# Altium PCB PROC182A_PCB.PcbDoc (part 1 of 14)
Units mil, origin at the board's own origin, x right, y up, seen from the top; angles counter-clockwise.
Board outline 3168.31 x 3700.79 mil, 8 copper layers (Top Layer, L2_GND1, L3_SIG1, L4_PWR1, L5_PWR2, L6_SIG2, L7_GND2, Bottom Layer), stack 58.1 mil thick; 580 components, 391 nets, 8314 pads, 4370 vias.
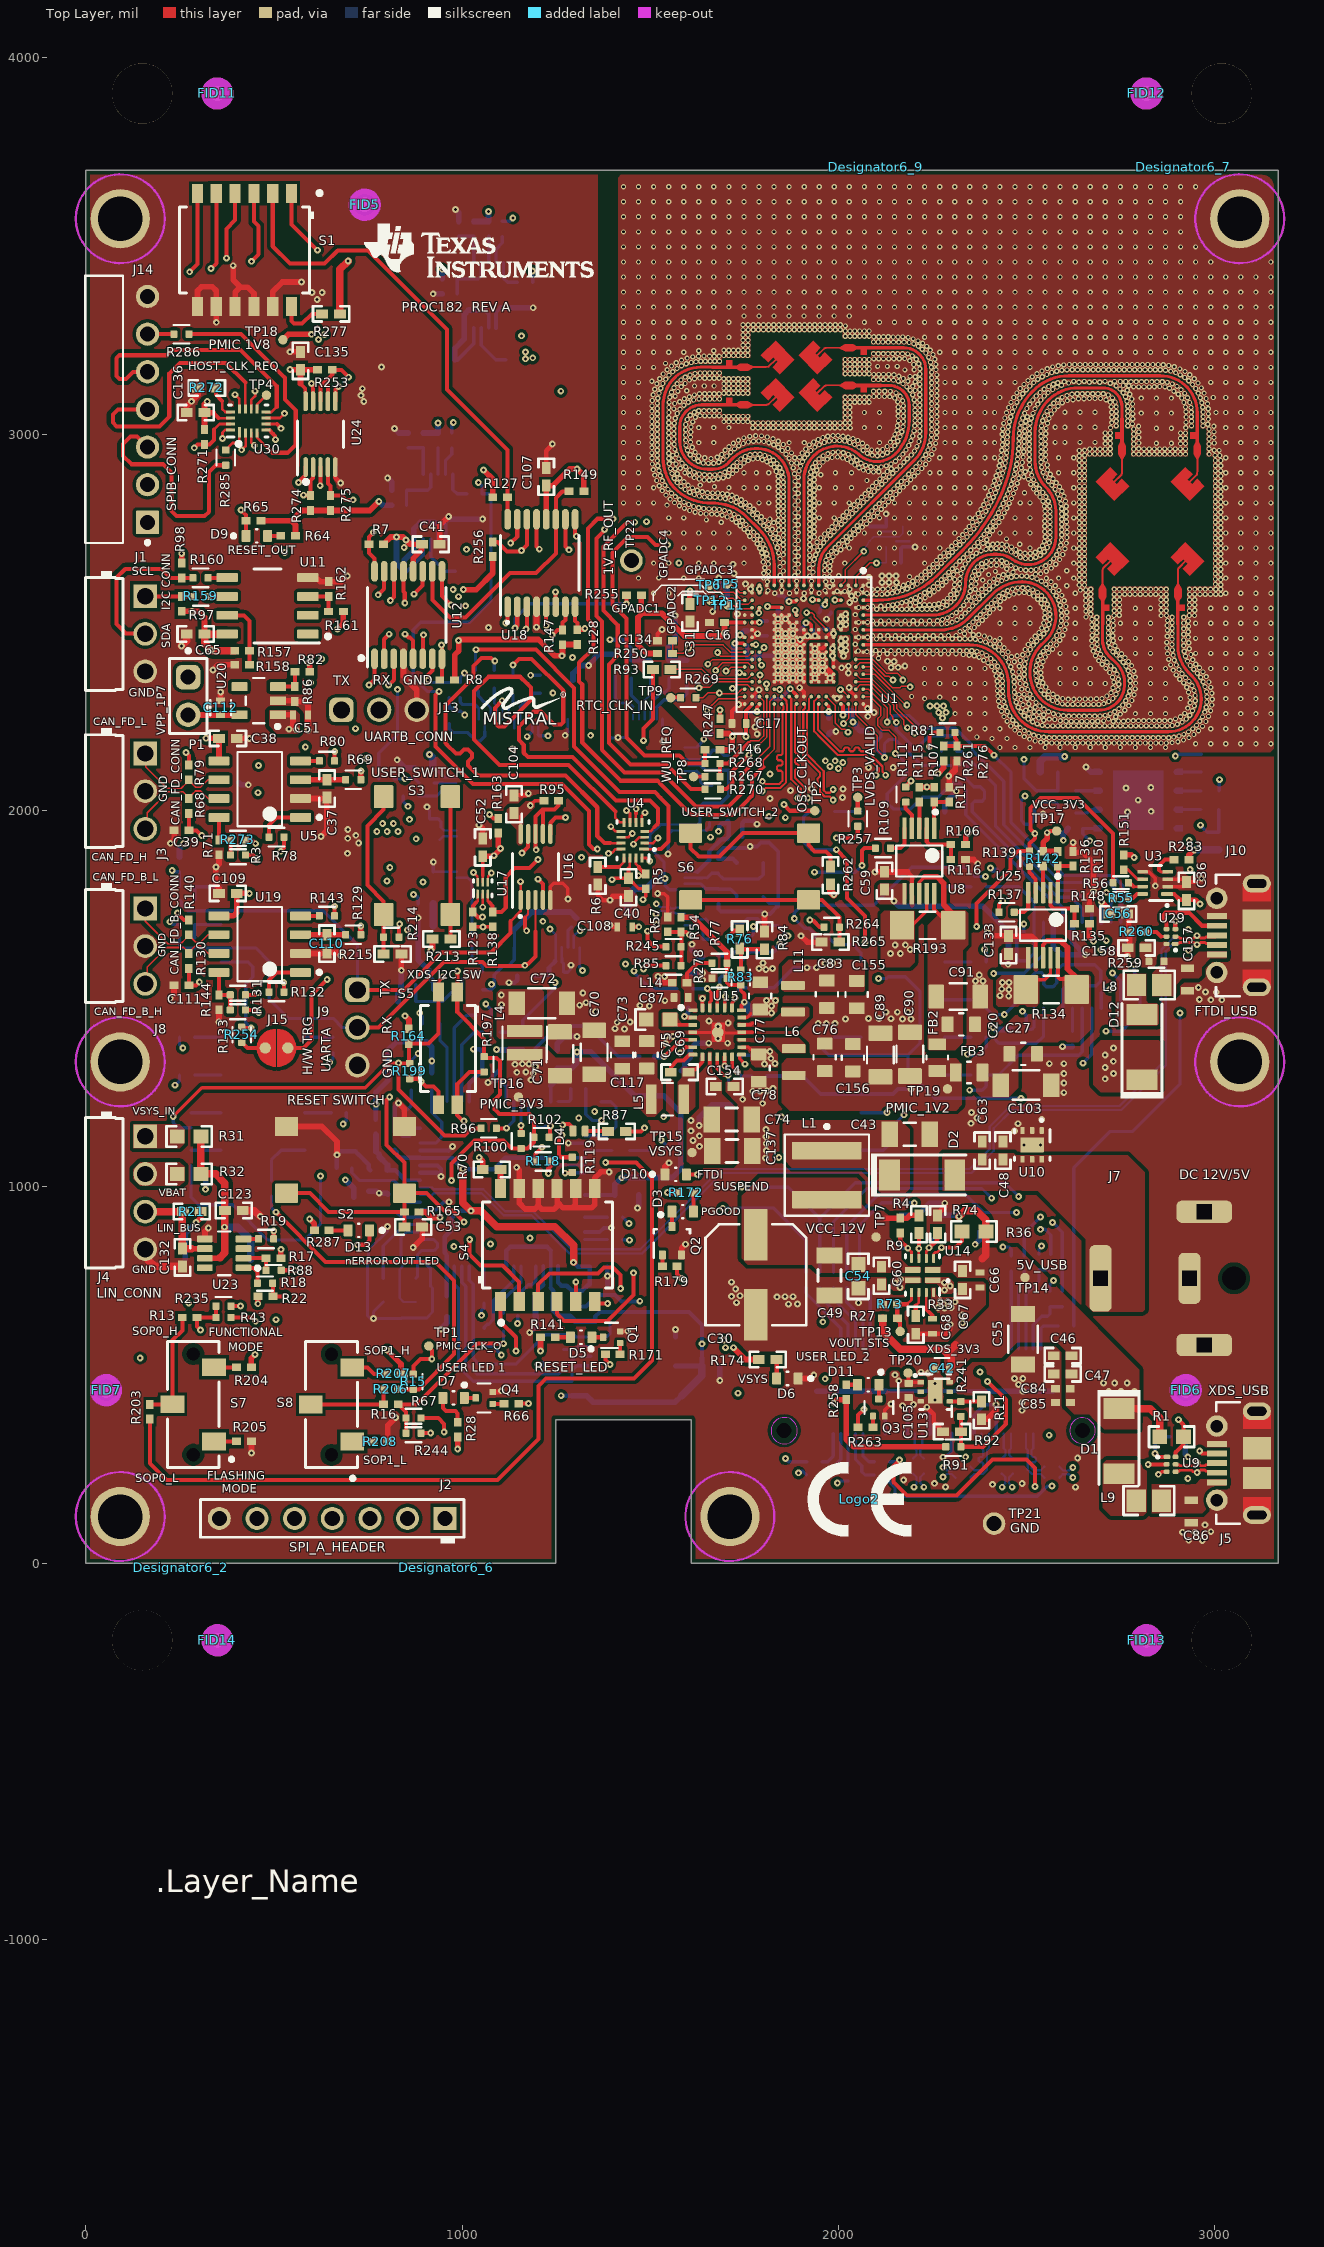
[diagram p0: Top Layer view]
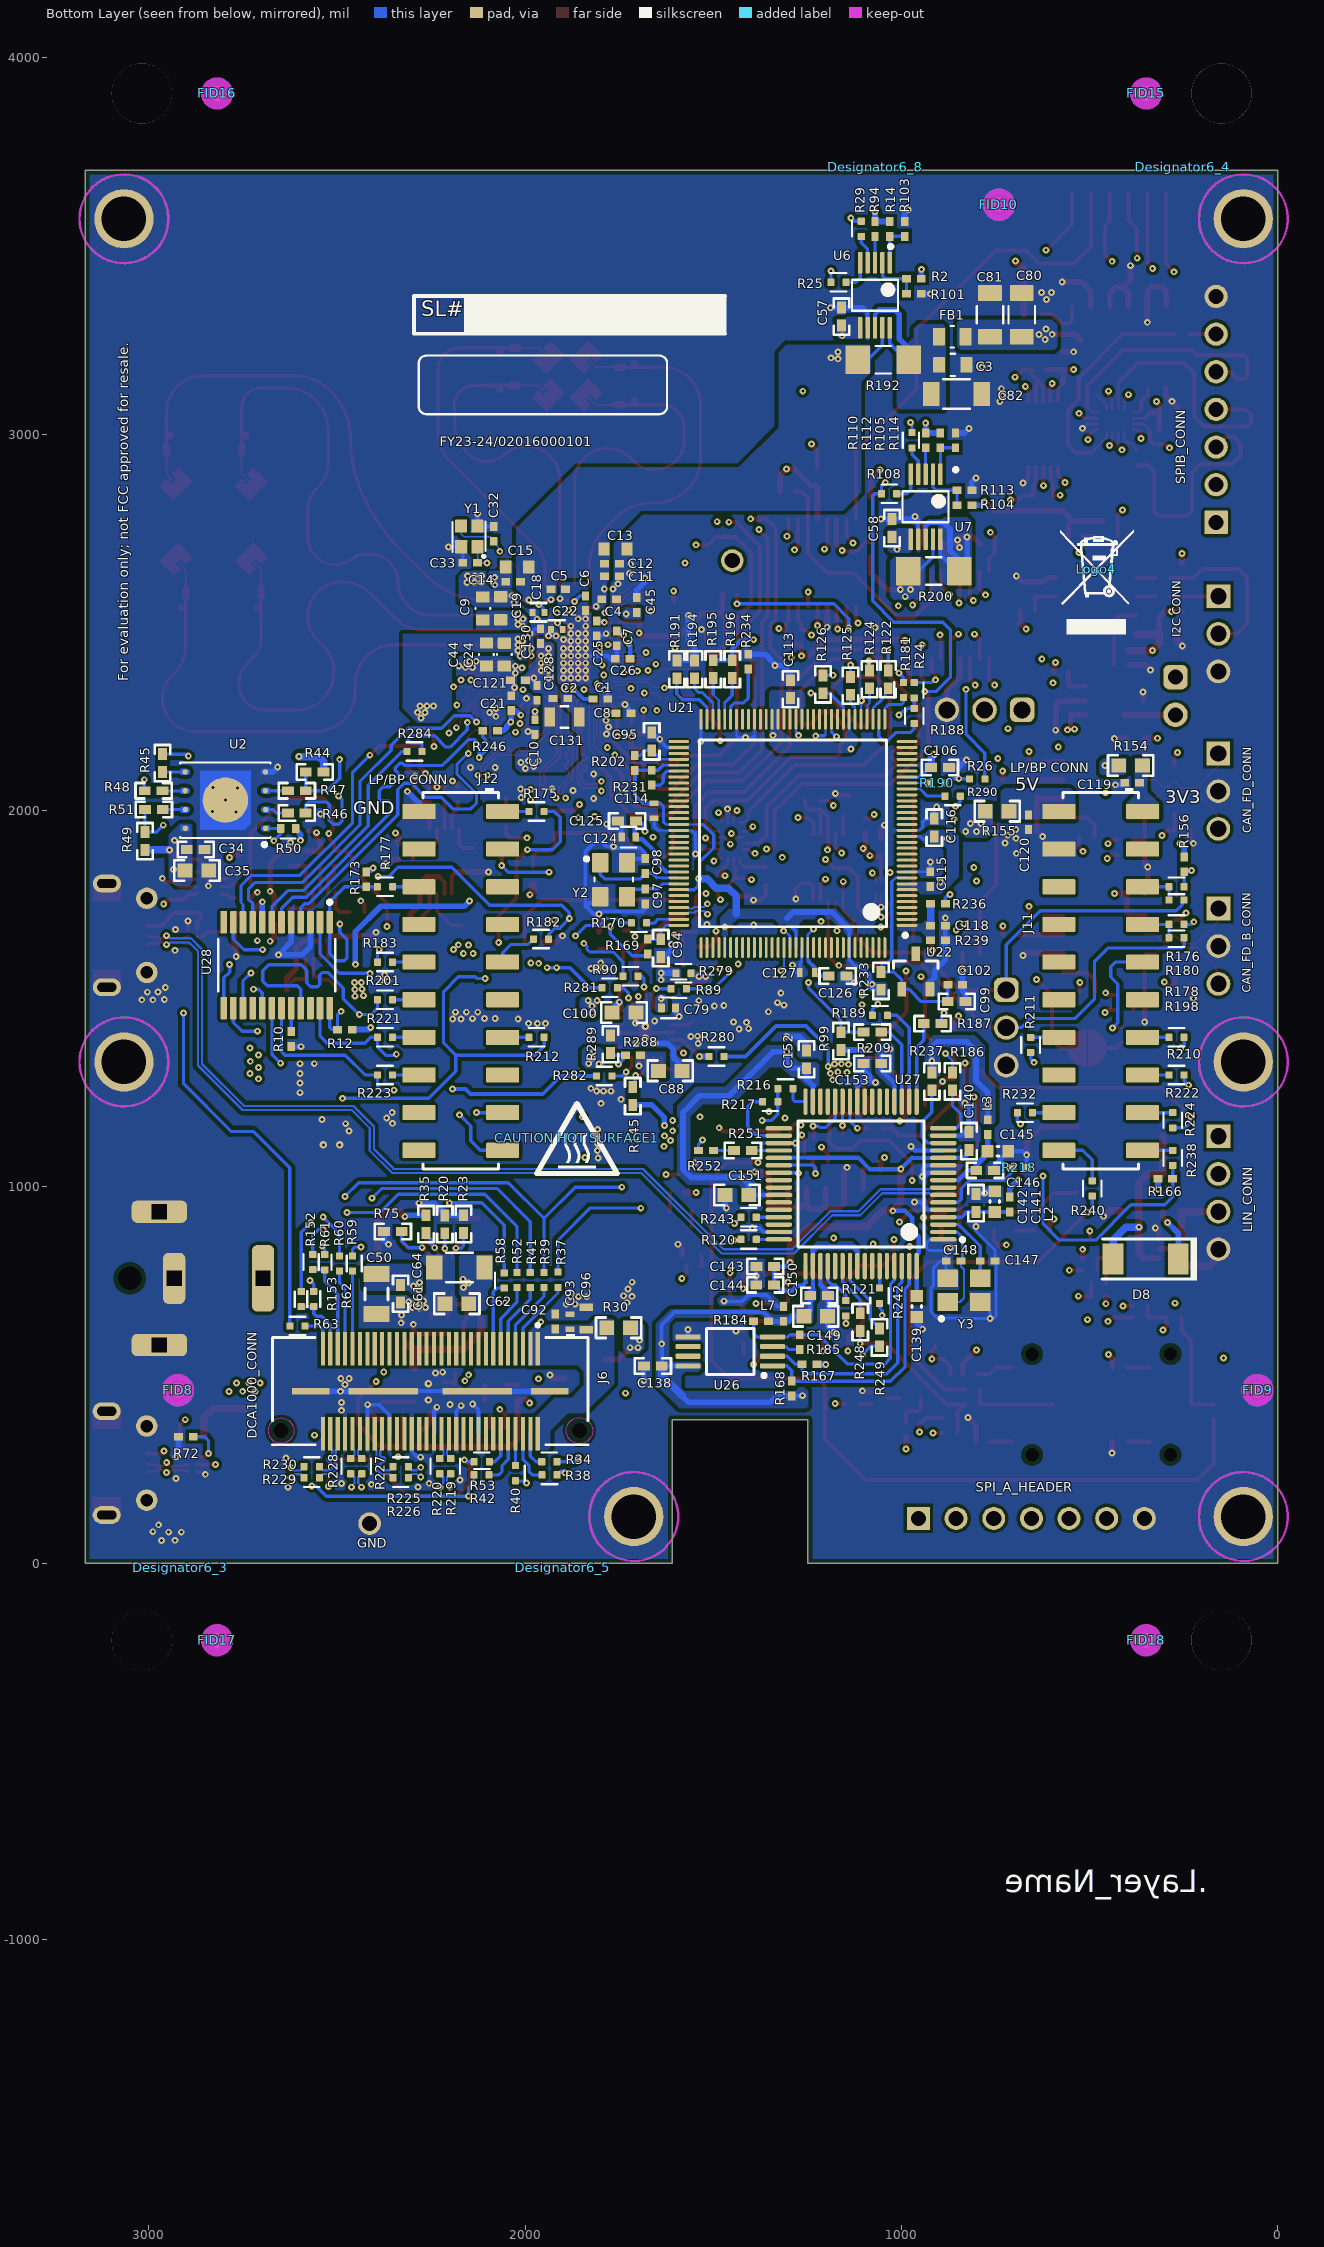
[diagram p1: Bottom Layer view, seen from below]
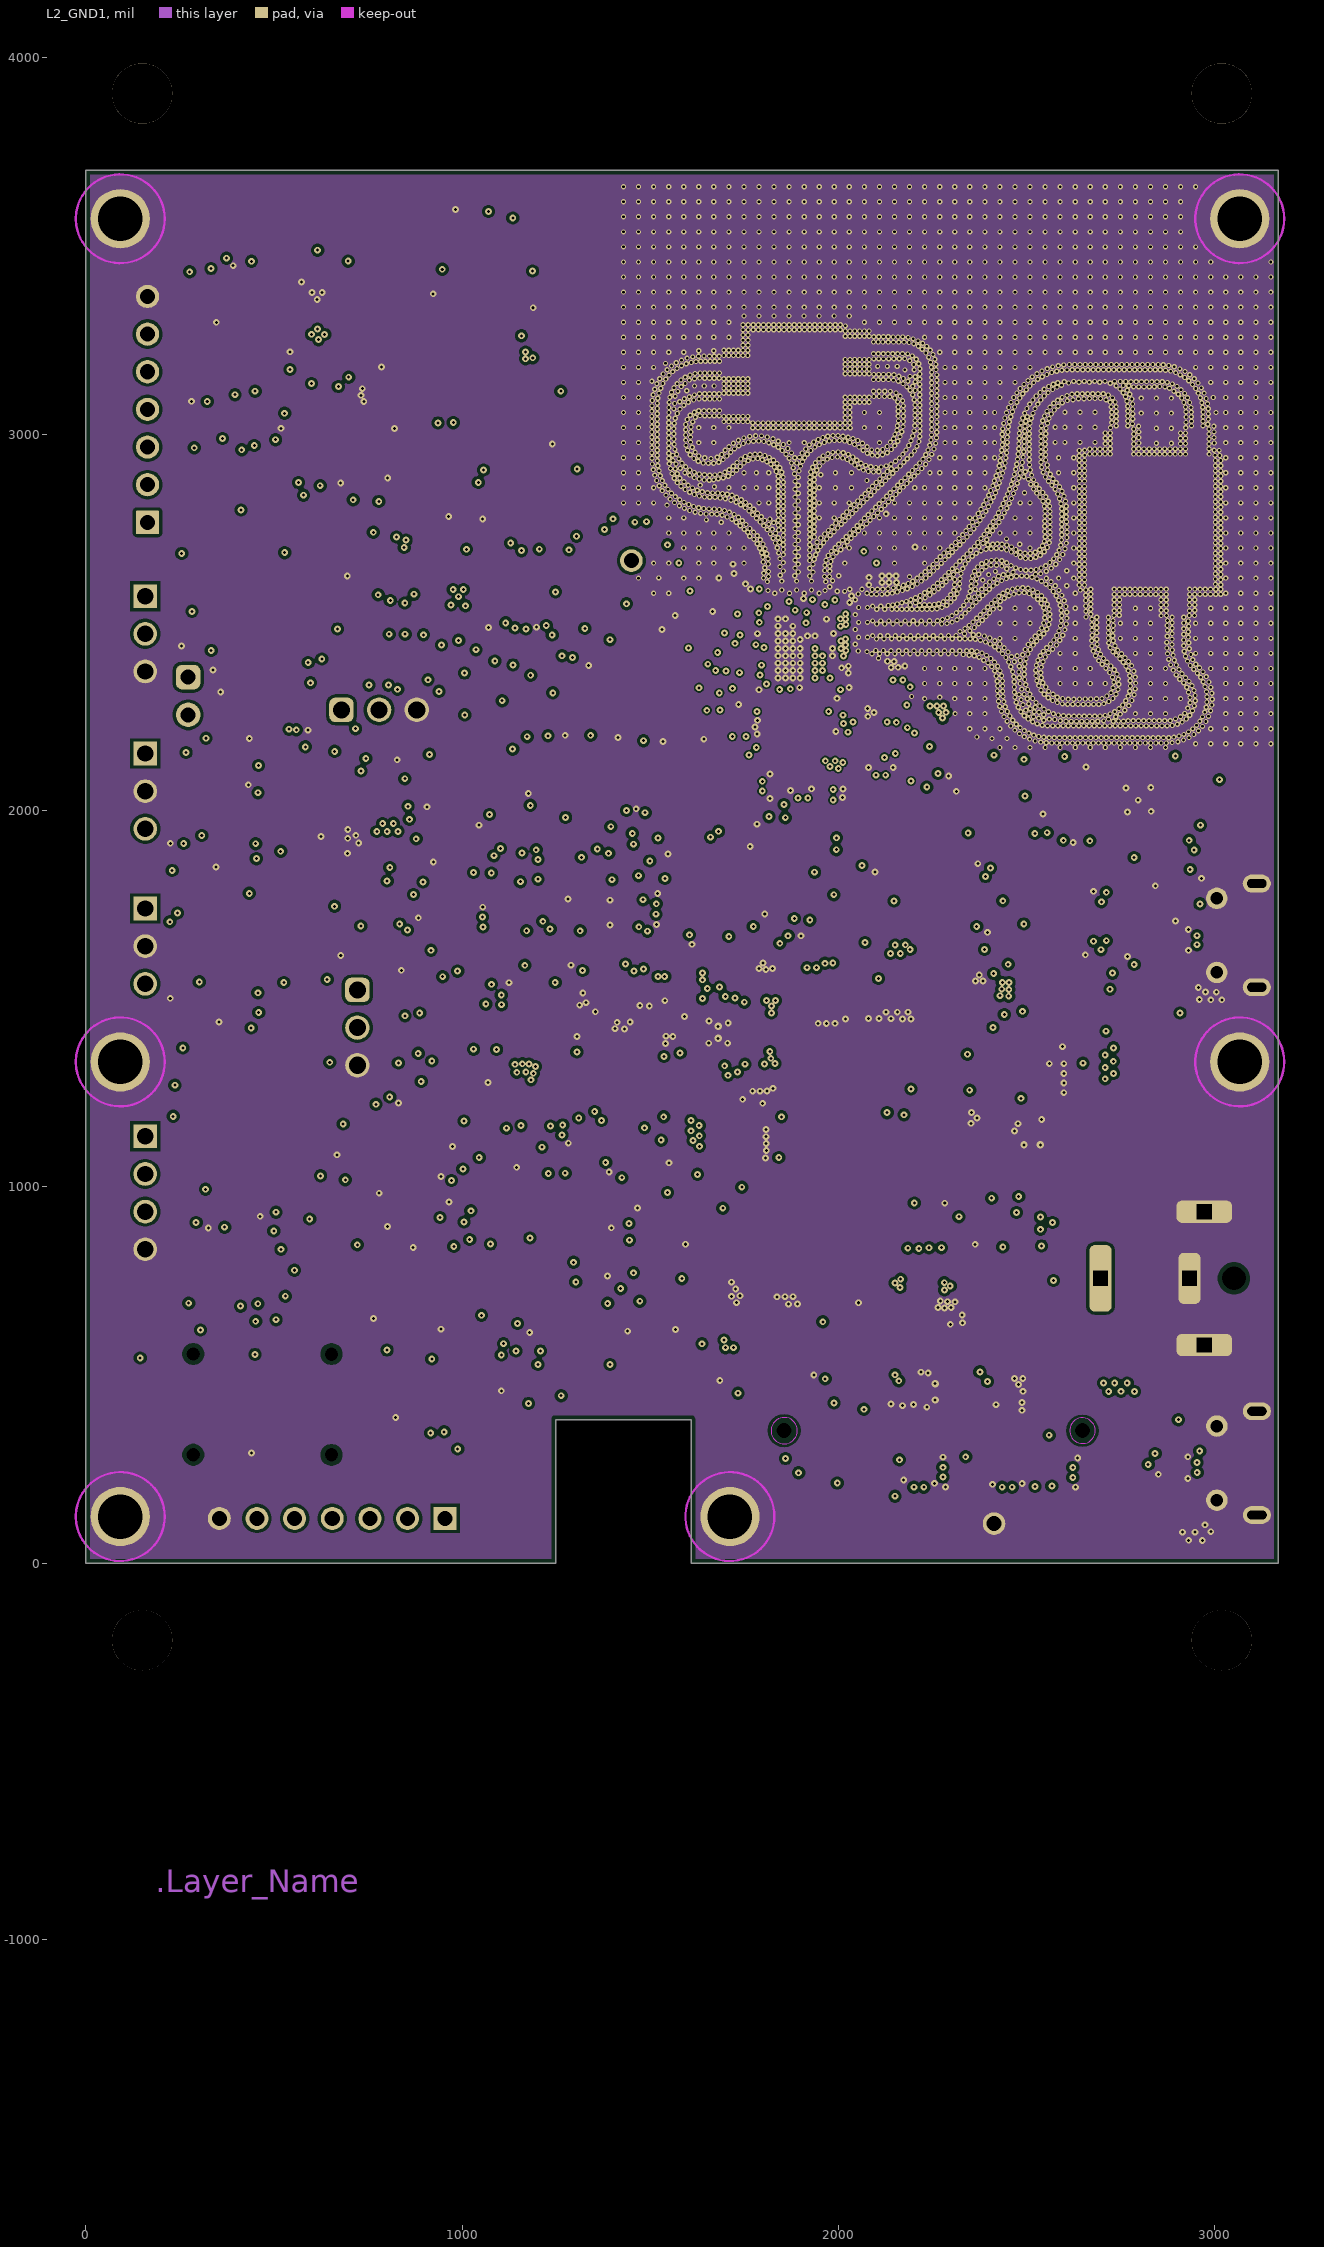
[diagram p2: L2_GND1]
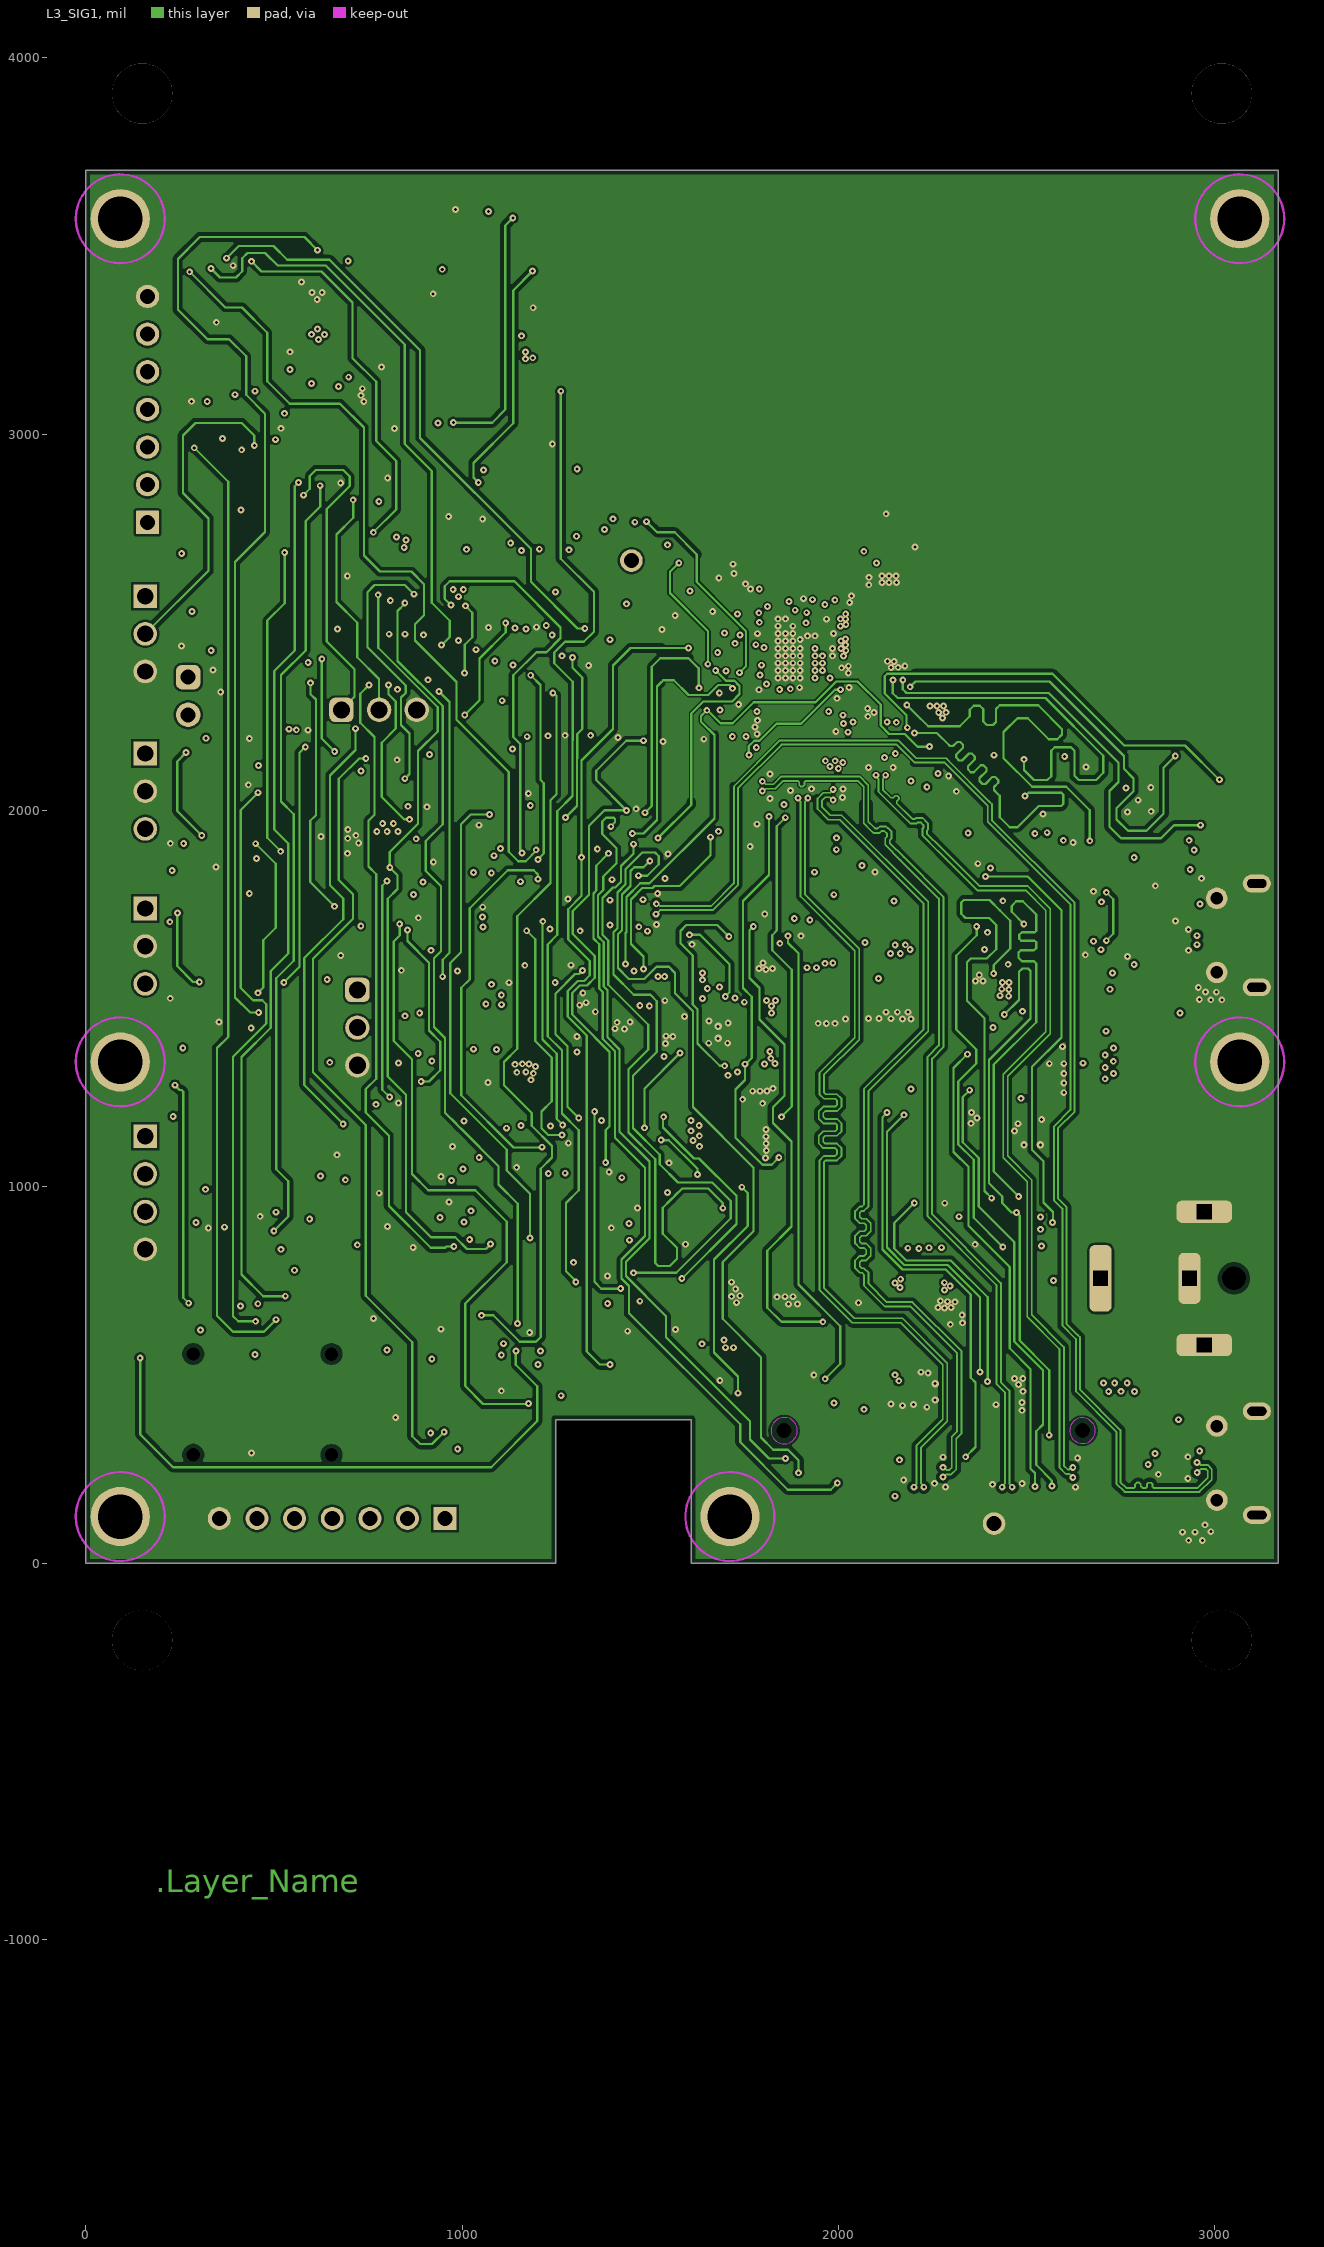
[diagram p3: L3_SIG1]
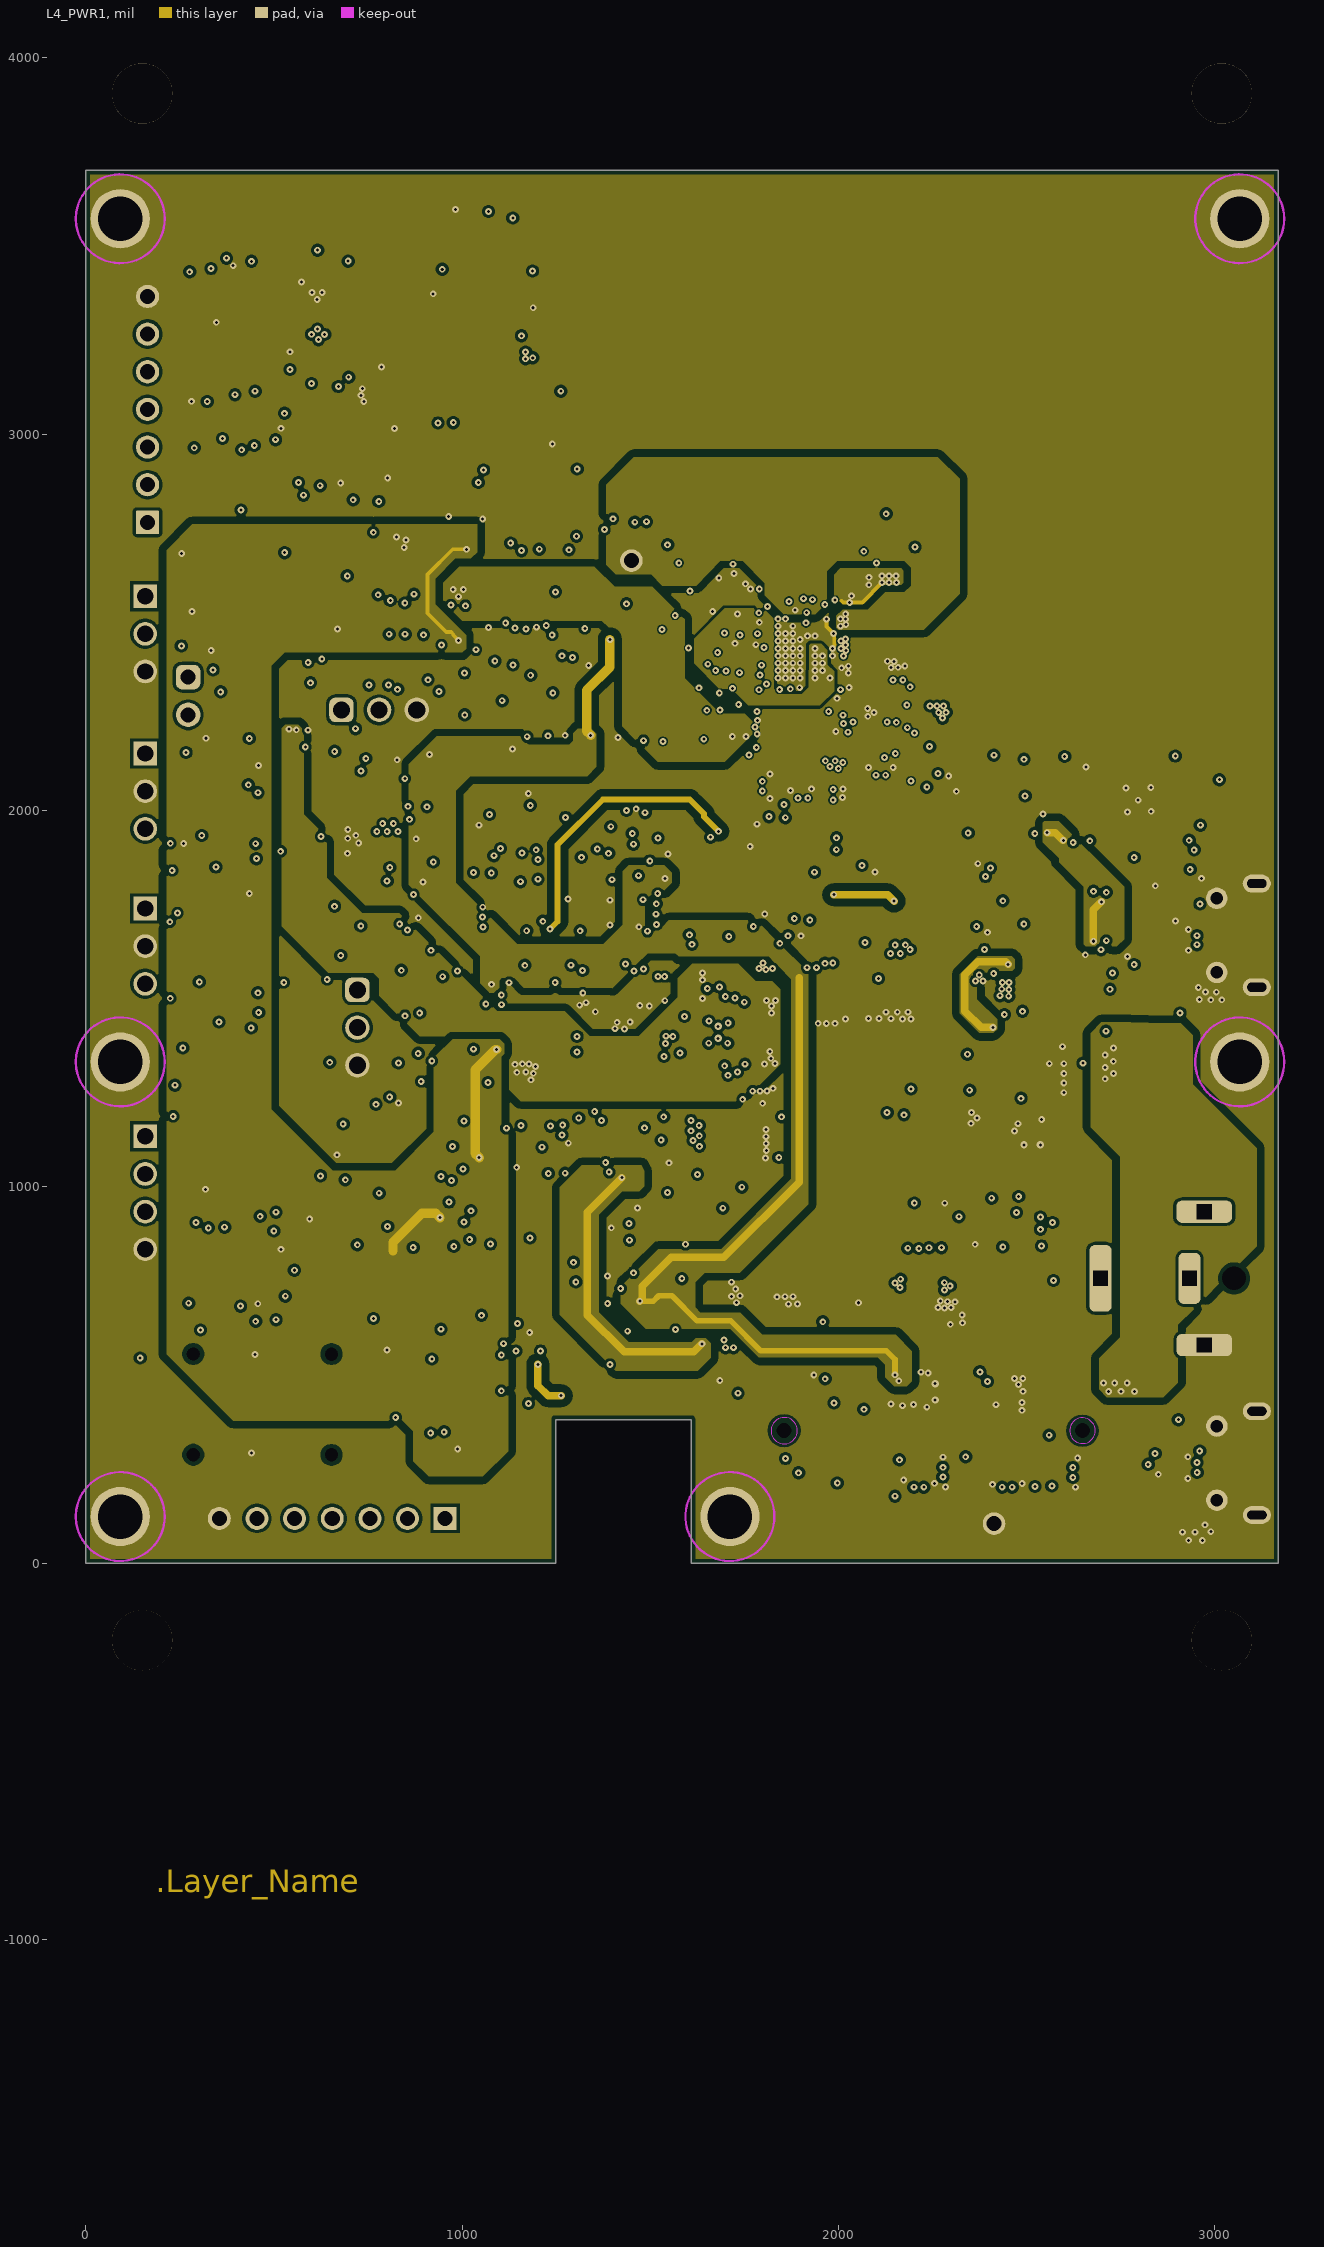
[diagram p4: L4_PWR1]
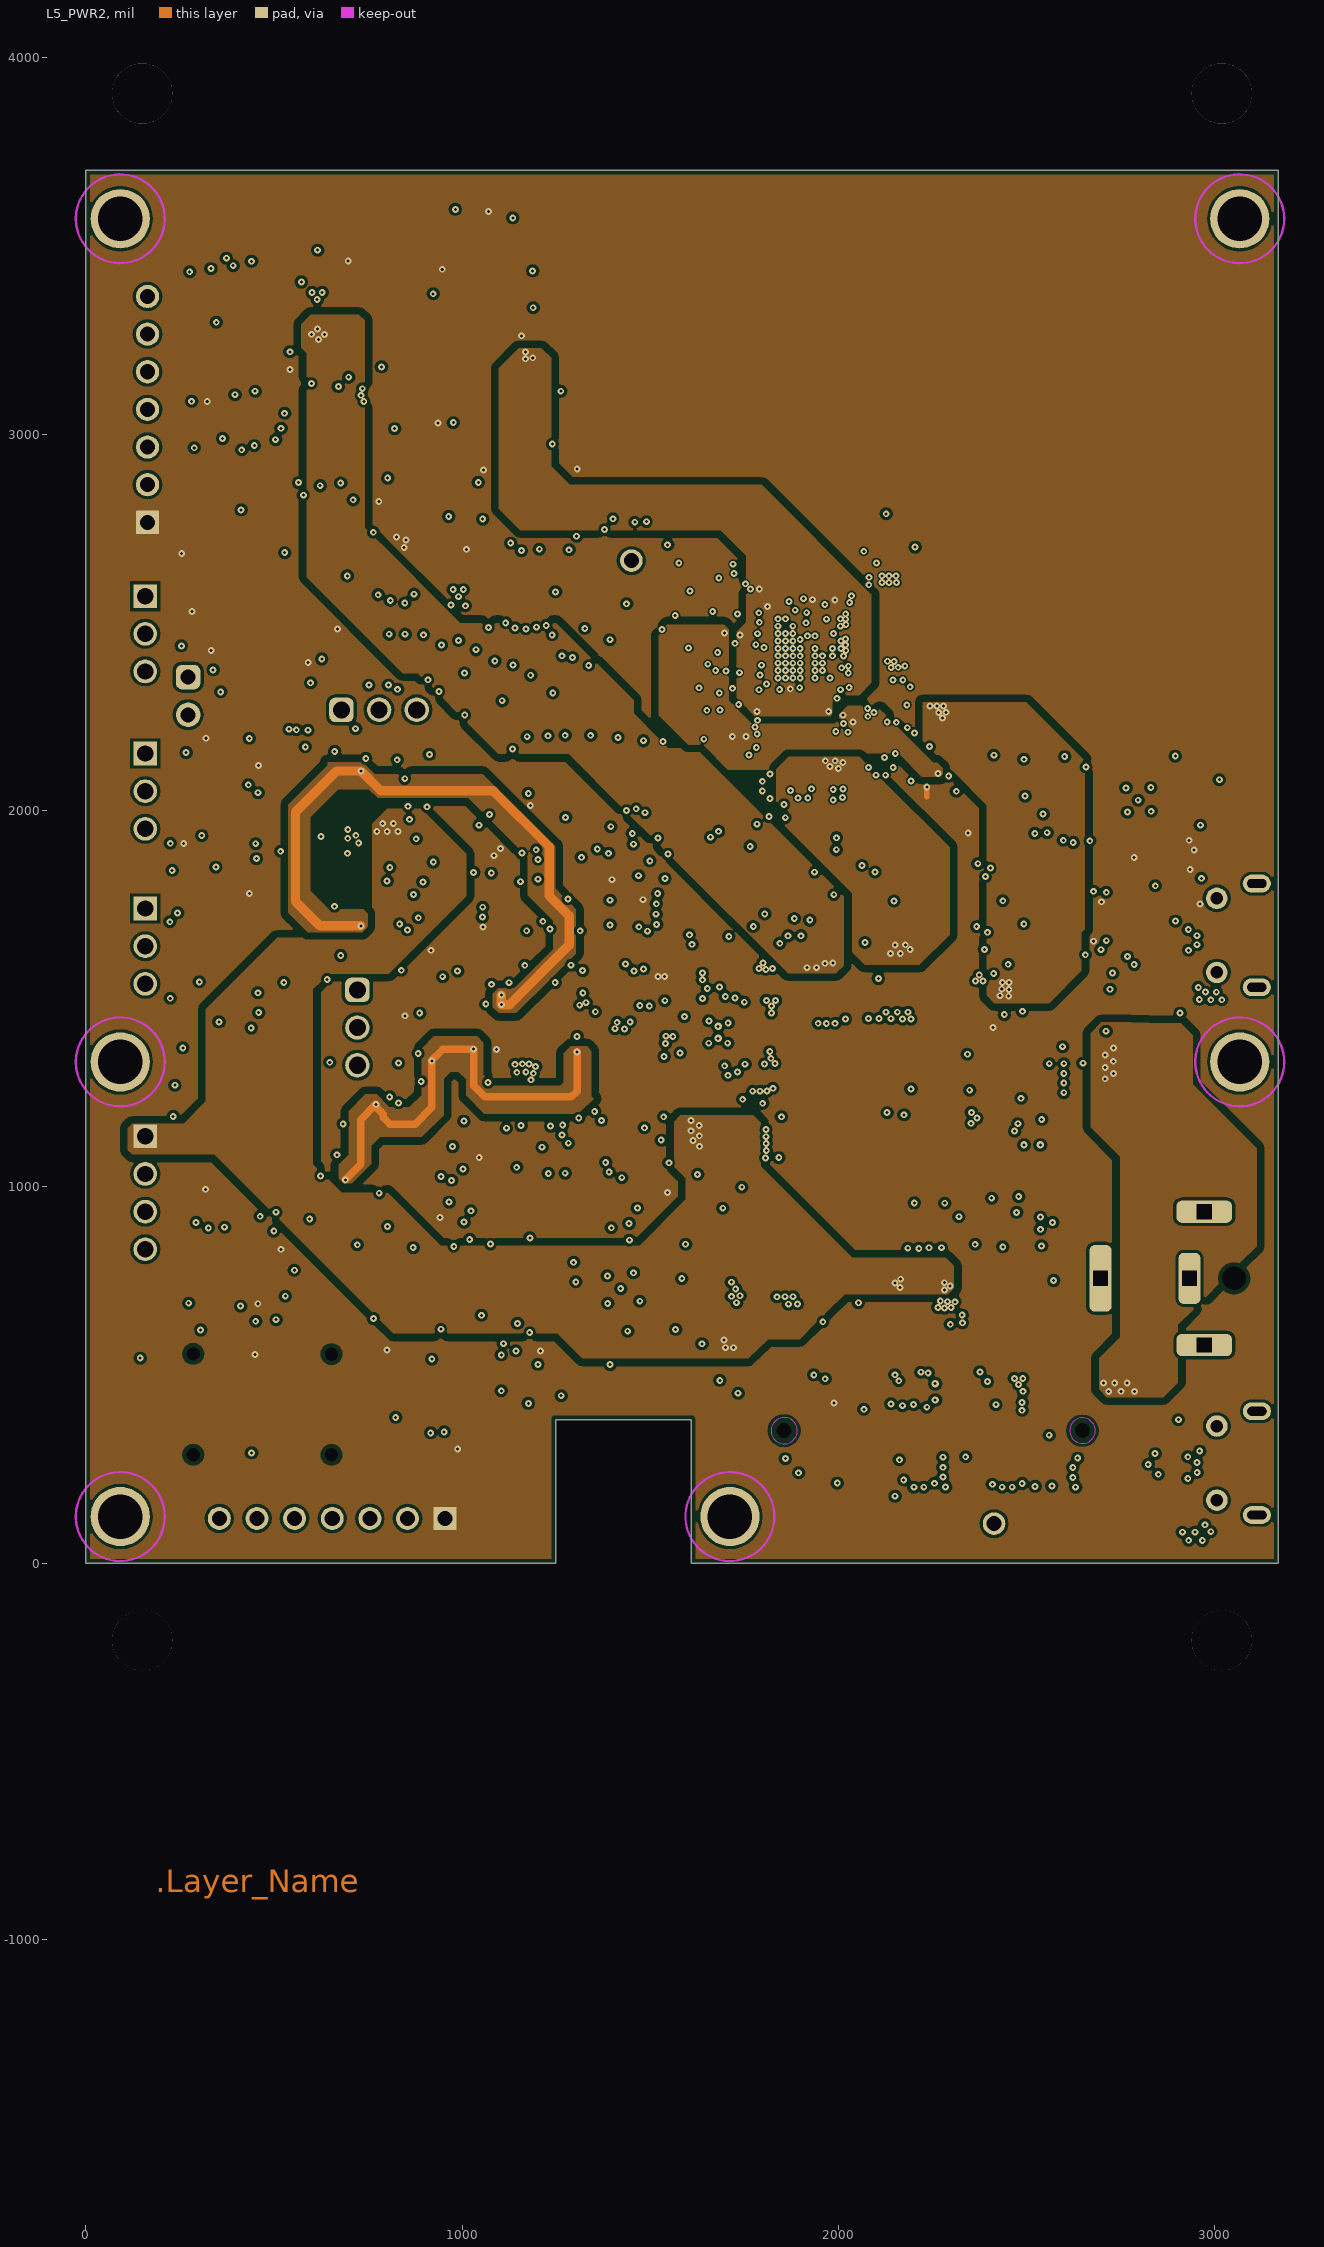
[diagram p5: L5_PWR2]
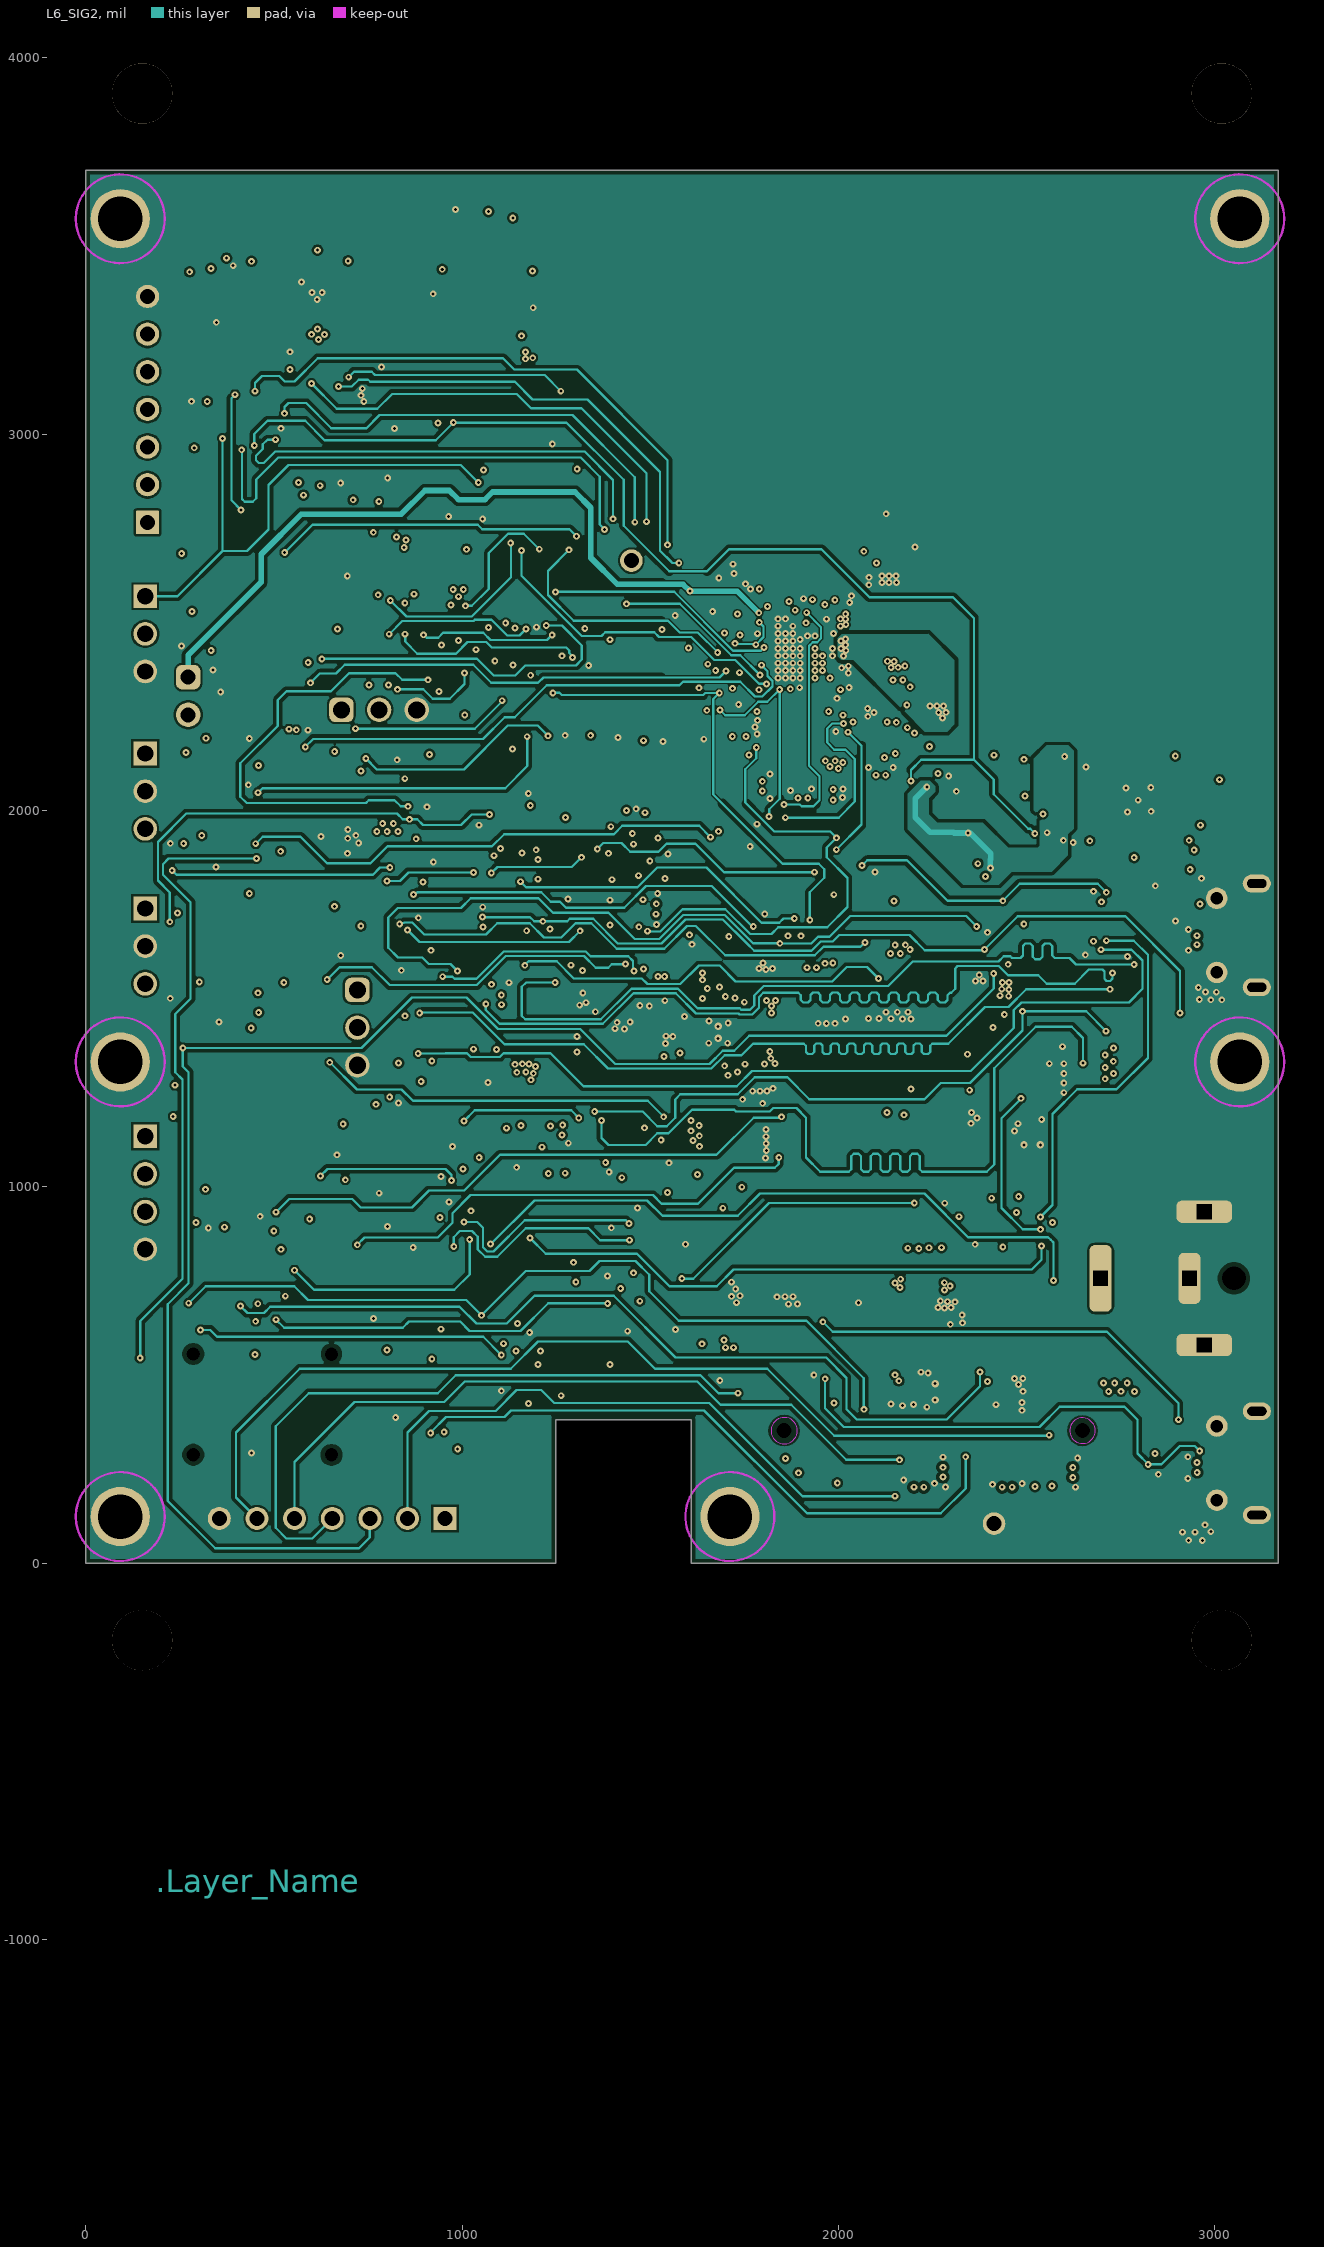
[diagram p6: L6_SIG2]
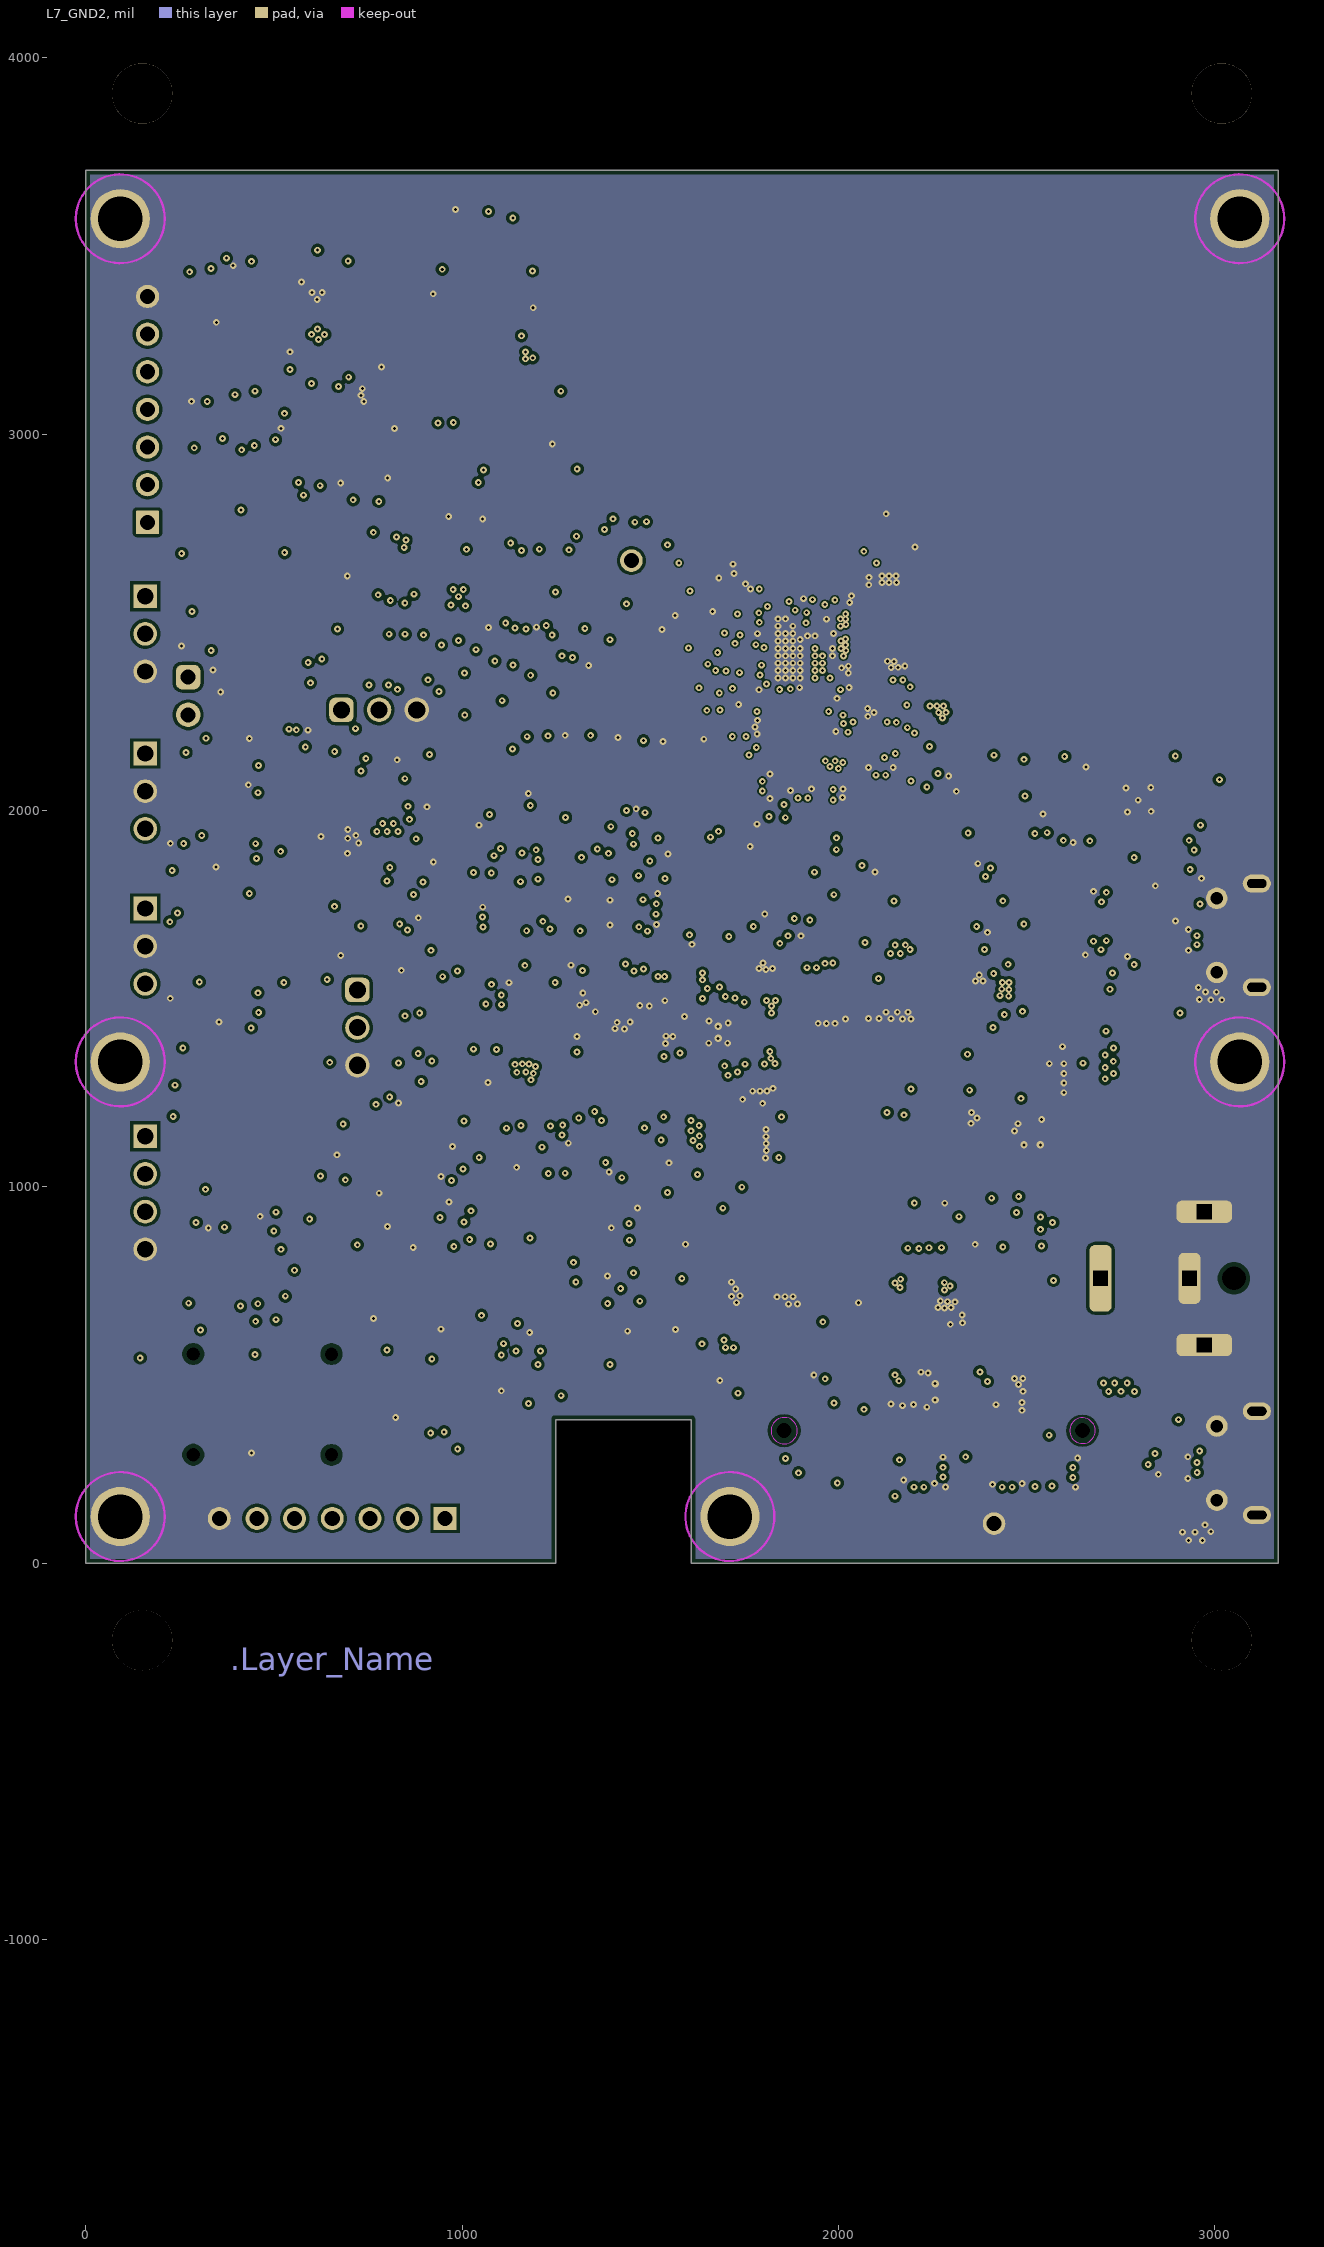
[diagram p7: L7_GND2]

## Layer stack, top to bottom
Top Solder: solder mask 0.8, Solder Resist, Dk 1
Top Layer: signal copper 1.6
Dielectric 1: core 5, RO3003, Dk 3
L2_GND1: signal copper 1.4
Dielectric 2: prepreg 5.5, PCL370HR, Dk 3.9
L3_SIG1: signal copper 1.4
Dielectric 3: core 10, PCL370HR, Dk 4.25
L4_PWR1: signal copper 1.4
Dielectric 4: prepreg 5.5, PCL370HR, Dk 3.9
L5_PWR2: signal copper 1.4
Dielectric 5: prepreg 10, PCL370HR, Dk 4.25
L6_SIG2: signal copper 1.4
Dielectric 6: core 5.5, PCL370HR, Dk 3.9
L7_GND2: signal copper 1.4
Dielectric 7: core 5, PCL370HR, Dk 4.25
Bottom Layer: signal copper 1.6
Bottom Solder: solder mask 0.8, Solder Resist, Dk 1

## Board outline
0,0 0,3700.79 3168.31,3700.79 3168.31,0 1608.62,0 1608.62,381.95 1248.62,381.95 1248.62,0

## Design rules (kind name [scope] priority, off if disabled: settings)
AcuteAngle [All] p1 off: minimum=4.50000000000000E+0001 checktracksonly=FALSE
AssemblyTestPointUsage [All] p1: valid=2
BoardOutlineClearance [All] p1: gap=12 ignorepadtopadclearanceinfootprint=FALSE
Clearance Diff_DRC_Clear [InAnyDifferentialPair vs InAnyDifferentialPair] p1: gap=3 ignorepadtopadclearanceinfootprint=TRUE
Clearance "Clearance_TX and RX" [InNetClass('TX and RX')] p2: gap=3.94 ignorepadtopadclearanceinfootprint=FALSE except(4: Arc-Text Track-Text SMDPad-Text THPad-Text Via-Text Fill-Text Poly-Text Region-Text Text-Text; 6: Arc-Hole Track-Hole SMDPad-Via SMDPad-Hole THPad-Hole Via-Hole Fill-Hole Poly-Hole Region-Hole Text-Hole; 7.7: Fill-Fill Fill-Poly; 8: Arc-Arc Arc-Track Track-Track SMDPad-Fill SMDPad-Poly SMDPad-Region THPad-Fill THPad-Poly THPad-Region Via-Via Via-Fill Via-Poly; 9: SMDPad-SMDPad; 10: Arc-SMDPad Arc-THPad Track-SMDPad Track-THPad SMDPad-THPad THPad-THPad THPad-Via)
Clearance Clearance_BGA [WithinRoom('BGA1')] p3: gap=4 ignorepadtopadclearanceinfootprint=FALSE except(8: Fill-Fill Fill-Poly Fill-Region Poly-Poly Poly-Region Region-Region)
Clearance 90E_Inner_layer_diff [InDifferentialPairClass('90E') vs InLayerClass('External_layers') or InLayerClass('Inner_sig_layer')] p4: gap=8 ignorepadtopadclearanceinfootprint=TRUE except(0: Text-Hole; 5: Track-SMDPad; 6: Track-Via; 10: Track-Poly Fill-Fill Fill-Poly Fill-Region Poly-Poly Poly-Region Region-Region; 11: Fill-Hole Poly-Hole Region-Hole; 12: Track-Track Track-THPad)
Clearance 100E_Inner_layer [InDifferentialPairClass('100E') vs InLayerClass('Inner_sig_layer')] p5: gap=8 ignorepadtopadclearanceinfootprint=TRUE except(0: Text-Hole; 10: Track-Poly Fill-Fill Fill-Poly Fill-Region Poly-Poly Poly-Region Region-Region; 11: Fill-Hole Poly-Hole Region-Hole; 12: Track-Track Track-SMDPad Track-THPad)
Clearance 100E_OUTER_LAYER [InDifferentialPairClass('100E') vs InLayerClass('External_layers')] p6: gap=8 ignorepadtopadclearanceinfootprint=TRUE except(0: Text-Hole; 10: Track-Poly Fill-Fill Fill-Poly Fill-Region Poly-Poly Poly-Region Region-Region; 11: Fill-Hole Poly-Hole Region-Hole; 12: Track-SMDPad Track-THPad; 20: Track-Track)
Clearance 90E_Inner_layer [InDifferentialPairClass('90E') vs InLayerClass('Inner_sig_layer')] p7: gap=8 ignorepadtopadclearanceinfootprint=TRUE except(0: Text-Hole; 10: Track-Track Track-Poly Fill-Fill Fill-Poly Fill-Region Poly-Poly Poly-Region Region-Region; 11: Fill-Hole Poly-Hole Region-Hole; 12: Track-SMDPad Track-THPad)
Clearance Clearance_BOTTOM [OnBottomLayer] p8: gap=8 ignorepadtopadclearanceinfootprint=TRUE except(0: Text-Hole; 3.9: Track-Track; 6: Track-SMDPad; 10: Track-Poly Fill-Fill Fill-Poly Fill-Region Poly-Poly Poly-Region Region-Region; 11: Fill-Hole Poly-Hole Region-Hole)
Clearance Clearance_TOP [OnTopLayer] p9: gap=8 ignorepadtopadclearanceinfootprint=TRUE except(0: Text-Hole; 5: Via-Region Region-Region; 5.5: Track-Track; 6: Track-SMDPad Track-Via SMDPad-SMDPad SMDPad-Via; 10: Track-Poly Fill-Fill Fill-Poly Fill-Region Poly-Poly Poly-Region; 11: Fill-Hole Poly-Hole Region-Hole)
Clearance Clearance_INNER_LAYER [(OnLayer('L3_SIG1') OR OnLayer('L6_SIG2'))] p10: gap=6 ignorepadtopadclearanceinfootprint=TRUE except(0: Text-Hole; 10: Track-Poly Fill-Fill Fill-Poly Fill-Region Poly-Poly Poly-Region Region-Region; 11: Fill-Hole Poly-Hole Region-Hole)
Clearance [All] p11: gap=8 ignorepadtopadclearanceinfootprint=TRUE except(0: Text-Hole; 6: Arc-Hole Track-Track Track-Text Track-Hole; 10: Fill-Fill Fill-Poly Fill-Region Poly-Region Region-Region; 11: Fill-Hole Poly-Hole Region-Hole; 20: Track-Poly Poly-Poly)
Clearance Clearance_Keepout [IsKeepOut] p12: gap=0 ignorepadtopadclearanceinfootprint=TRUE
ComponentClearance ComponentClearance_MatingCon-3D [All vs not InAnyComponent] p1: gap=0 collisioncheckmode=3 verticalgap=0 showdistances=FALSE
ComponentClearance "ComponentClearance_WEE Logo" [InComponent('Logo4')] p2: gap=0 collisioncheckmode=3 verticalgap=0 showdistances=TRUE
ComponentClearance ComponentClearance_R77 [InComponent('R77') vs InComponent('Logo1')] p3: gap=0 collisioncheckmode=3 verticalgap=0 showdistances=TRUE
ComponentClearance ComponentClearance_Logo [InComponentClass('Logo')] p4: gap=0 collisioncheckmode=3 verticalgap=0 showdistances=TRUE
ComponentClearance "ComponentClearance_Mounting Holes_Fiducial Marks" [InComponentClass('FiducialMark') vs InPadClass('Mounting Holes PADS')] p5: gap=50 collisioncheckmode=3 verticalgap=10 showdistances=TRUE
ComponentClearance [All] p6: gap=6 collisioncheckmode=3 verticalgap=10 showdistances=TRUE
DiffPairsRouting 120E [InDifferentialPairClass('120E')] p1: maxlimit=10 minlimit=5.5 mostfreqgap=10 toplayer_maxgap=5.5 toplayer_prefgap=5.5 toplayer_minwidth=4.3 toplayer_maxwidth=4.3 toplayer_prefwidth=4.3 midlayer1_mingap=10 midlayer1_minwidth=15 midlayer1_maxwidth=15 midlayer1_prefwidth=15 midlayer2_mingap=9.8 midlayer2_maxgap=9.8 midlayer2_prefgap=9.8 midlayer2_minwidth=3.1 midlayer2_maxwidth=3.1 midlayer2_prefwidth=3.1 midlayer3_mingap=10 midlayer3_minwidth=15 midlayer3_maxwidth=15 midlayer3_prefwidth=15 midlayer4_mingap=10 midlayer4_minwidth=15 midlayer4_maxwidth=15 midlayer4_prefwidth=15 midlayer5_mingap=10 midlayer5_minwidth=15 midlayer5_maxwidth=15 midlayer5_prefwidth=15 midlayer6_mingap=9.8 midlayer6_maxgap=9.8 midlayer6_prefgap=9.8 midlayer6_minwidth=3.1 midlayer6_maxwidth=3.1 midlayer6_prefwidth=3.1 bottomlayer_mingap=5.9 bottomlayer_maxgap=5.9 bottomlayer_prefgap=5.9 bottomlayer_minwidth=4.7 bottomlayer_maxwidth=4.7 bottomlayer_prefwidth=4.7 maxuncoupledlength=500
DiffPairsRouting 100E [InDifferentialPairClass('100E')] p2: maxlimit=10 minlimit=3.9 mostfreqgap=10 toplayer_mingap=4.2 toplayer_maxgap=4.2 toplayer_prefgap=4.2 toplayer_minwidth=5.8 toplayer_maxwidth=5.8 toplayer_prefwidth=5.8 midlayer1_mingap=10 midlayer1_minwidth=15 midlayer1_maxwidth=15 midlayer1_prefwidth=15 midlayer2_mingap=7.2 midlayer2_maxgap=7.2 midlayer2_prefgap=7.2 midlayer2_minwidth=4.8 midlayer2_maxwidth=4.8 midlayer2_prefwidth=4.8 midlayer3_mingap=10 midlayer3_minwidth=15 midlayer3_maxwidth=15 midlayer3_prefwidth=15 midlayer4_mingap=10 midlayer4_minwidth=15 midlayer4_maxwidth=15 midlayer4_prefwidth=15 midlayer5_mingap=10 midlayer5_minwidth=15 midlayer5_maxwidth=15 midlayer5_prefwidth=15 midlayer6_mingap=7.2 midlayer6_maxgap=7.2 midlayer6_prefgap=7.2 midlayer6_minwidth=4.8 midlayer6_maxwidth=4.8 midlayer6_prefwidth=4.8 bottomlayer_maxgap=3.9 bottomlayer_prefgap=3.9 bottomlayer_minwidth=5.9 bottomlayer_maxwidth=5.9 bottomlayer_prefwidth=5.9 maxuncoupledlength=500
DiffPairsRouting 90E [InDifferentialPairClass('90E')] p3: maxlimit=10 minlimit=4 mostfreqgap=10 toplayer_maxgap=4 toplayer_prefgap=4 toplayer_minwidth=7.5 toplayer_maxwidth=7.5 toplayer_prefwidth=7.5 midlayer1_mingap=10 midlayer1_minwidth=15 midlayer1_maxwidth=15 midlayer1_prefwidth=15 midlayer2_mingap=5.9 midlayer2_maxgap=5.9 midlayer2_prefgap=5.9 midlayer2_minwidth=5 midlayer2_maxwidth=5 midlayer2_prefwidth=5 midlayer3_mingap=10 midlayer3_minwidth=15 midlayer3_maxwidth=15 midlayer3_prefwidth=15 midlayer4_mingap=10 midlayer4_minwidth=15 midlayer4_maxwidth=15 midlayer4_prefwidth=15 midlayer5_mingap=10 midlayer5_minwidth=15 midlayer5_maxwidth=15 midlayer5_prefwidth=15 midlayer6_mingap=5.9 midlayer6_maxgap=5.9 midlayer6_prefgap=5.9 midlayer6_minwidth=5 midlayer6_maxwidth=5 midlayer6_prefwidth=5 bottomlayer_mingap=5 bottomlayer_maxgap=5 bottomlayer_prefgap=5 bottomlayer_minwidth=6 bottomlayer_maxwidth=6 bottomlayer_prefwidth=6 maxuncoupledlength=500
FabricationTestPointUsage TestPointUsage [All] p1: valid=2 allowmultiple=FALSE
FabricationTestpoint Testpoint [All] p1: side=3 testpointundercomponent=TRUE minsize=40 maxsize=100 preferedsize=60 minholesize=0 maxholesize=40 preferedholesize=32 testpointgrid=1 allowsidetop=TRUE allowsidebottom=TRUE usegrid=TRUE gridtolerance=0.01
FanoutControl Fanout_LCC [IsLCC] p1: bgadir=Out bgaviamode=Centered fanoutstyle=Auto fanoutdirection=Alternating viagrid=1 // Fanout_LCC (Default Rule)
FanoutControl Fanout_BGA [IsBGA] p2: bgadir=Out bgaviamode=Centered fanoutstyle=Auto fanoutdirection=Alternating viagrid=1 // Fanout_BGA (Default Rule)
FanoutControl Fanout_Default [All] p4: bgadir=Out bgaviamode=Centered fanoutstyle=Auto fanoutdirection=Alternating viagrid=1 // Fanout_Default (Default Rule)
FanoutControl Fanout_Small [(CompPinCount < 5)] p5: bgadir=Out bgaviamode=Centered fanoutstyle=Auto fanoutdirection=OutThenIn viagrid=1 // Fanout_Small (Default Rule)
Height Room_Hieght [WithinRoom('Room_Hieght 1 MM')] p1: minheight=0 maxheight=41.34 prefheight=39.37
HoleSize [All] p1: absolutevalues=TRUE maxlimit=280 minlimit=5.9 maxpercent=80.000 minpercent=20.000
HoleToHoleClearance HoleToHoleClearance_1 [WithinRoom('BGA1')] p1: gap=4 allowstackedmicrovias=FALSE
MatchedLengths QSPI [InxSignalClass('QSPI')] p1: tolerance=10 checknetsindiffpair=FALSE checkdiffpairvsdiffpair=TRUE checkxsignals=TRUE checkothers=TRUE targetsourcename=QSPI_SCLK-NetR48_1_PP2
MatchedLengths USB [InDifferentialPairClass('90E')] p2: tolerance=2.5 checknetsindiffpair=TRUE checkdiffpairvsdiffpair=FALSE checkxsignals=FALSE checkothers=FALSE
MatchedLengths LM_DCA [InxSignalClass('DCA_JTAG')] p3: tolerance=50 checknetsindiffpair=FALSE checkdiffpairvsdiffpair=TRUE checkxsignals=TRUE checkothers=TRUE targetsourcename=DCA_TCK-NetJ6_6_PP1
MatchedLengths LM_XDS [InxSignalClass('XDS_JTAG')] p4: tolerance=50 checknetsindiffpair=FALSE checkdiffpairvsdiffpair=TRUE checkxsignals=TRUE checkothers=TRUE targetsourcename=XDS_TCK-NetR122_1_PP1
MatchedLengths LM_XDS_DCA [InxSignalClass('XDS_DCA_JTAG')] p5: tolerance=50 checknetsindiffpair=FALSE checkdiffpairvsdiffpair=TRUE checkxsignals=TRUE checkothers=TRUE targetsourcename=XDS_DCA_TCK_PP1
MatchedLengths LM_FTDI_SPI [InxSignalClass('FTDI_SPI')] p6: tolerance=10 checknetsindiffpair=FALSE checkdiffpairvsdiffpair=TRUE checkxsignals=TRUE checkothers=TRUE targetsourcename=FTDI_SPI_CLK-FTDI_SPICLK_PP1
MatchedLengths LM_SPIB [InxSignalClass('SPIB')] p7: tolerance=10 checknetsindiffpair=FALSE checkdiffpairvsdiffpair=TRUE checkxsignals=TRUE checkothers=TRUE targetsourcename=I2C_SCL_SPIB_CLK_PP1
MatchedLengths DIFF_LVDS [InxSignalClass('LVDS')] p8: tolerance=2 checknetsindiffpair=TRUE checkdiffpairvsdiffpair=FALSE checkxsignals=FALSE checkothers=FALSE
MatchedLengths LM_LVDS [InxSignalClass('LVDS')] p9: tolerance=1.5 checknetsindiffpair=FALSE checkdiffpairvsdiffpair=TRUE checkxsignals=TRUE checkothers=TRUE targetsourcename=RADAR_LVDS_CLKM-NetJ6_46_PP1
MinimumAnnularRing MinimumAnnularRing_ThermalPadVias [IsVia and InAnyComponent] p1: minimumring=3.9
MinimumAnnularRing [All] p2: minimumring=3.9
MinimumSolderMaskSliver MinimumSolderMaskSliver_Logo [InComponentClass('Logo') vs InComponentClass('Logo')] p1: minsoldermaskwidth=0.7
MinimumSolderMaskSliver [All] p2: minsoldermaskwidth=3.5
PlaneConnect [All] p1: planeconnectstyle=Relief reliefexpansion=10 reliefentries=4 reliefconductorwidth=10 reliefairgap=10
PolygonConnect [All] p1: connectstyle=Direct reliefconductorwidth=10 reliefentries=4 polygonreliefangle="90 Angle" airgapwidth=10
RoomDefinition BGA1 [InComponentClass('Components Class 2')] p1: confinementstyle=ConfineIn formatcopy=TRUE lockcomponents=FALSE outline 1528.36,2691.42 2202.13,2691.42 2202.13,2018.79 1528.36,2018.79
RoutingVias [All] p1: holewidth=12.2 width=22.4 viastyle="Through Hole" minholewidth=5.9 minwidth=14 maxholewidth=20 maxwidth=40 useviatemplates=TRUE viatemplateguid#1={EDF544D5-CD1E-4F32-BA54-28702E8BDBDA} viatemplateguid#2={E2911D76-663B-4C28-95AD-0C427F46FF10} viatemplateguid#3={9E0678DD-4FAF-413B-9962-B5BD3FFA5594} viatemplateguid#4={C5C631FA-2ECB-421D-928B-ED62B3931DBB} viatemplateguid#5={27795D7D-BE5E-4326-85FD-36B33F06AFBC} viatemplateguid#6={555C4A8D-3D98-4753-BAEE-70F867978D87} viatemplateguid#7={4A1EF06F-3FD9-4CF7-BEA1-118D1CD21319} viatemplatename#1=v35h18(Tol8-8) viatemplatename#2=v46h20m0mx0(Tol8-8) viatemplatename#3=v46h20m0mx0(Tol8-8)(1) viatemplatename#4=v46h20m0mx92735(Tol8-8) viatemplatename#5=v50h20(Tol8-8) viatemplatename#6=v50h20m0mx0(Tol8-8) viatemplatename#7=v35h18m0(Tol8-8)
SMDToCorner [All] p1: distance=25000
SilkToBoardRegionClearance [Not ((IsComment or IsDesignator) And (Hide <> 'False')) and not InRegion(1000,500,4000,800)] p1:
SilkToSilkClearance [All] p1: silktosilkclearance=3
SilkToSolderMaskClearance SilkToSolderMaskClearance_OutLine [istrack and InAnyComponent] p1: minsilkscreentomaskgap=0 clearancetoexposedcopper=FALSE
SilkToSolderMaskClearance SilkscreenOverComponentPads [IsPad] p2: minsilkscreentomaskgap=3 clearancetoexposedcopper=FALSE
SolderMaskExpansion [All] p1: expansion=0 istentingtop=FALSE
UnRoutedNet [All] p1: checkbadconnections=TRUE
Width PWR [InNetClass('POWER')] p1: maxlimit=100 minlimit=6 preferedwidth=15 midlayer1_minwidth=10 midlayer1_maxwidth=10 midlayer1_prefwidth=10 midlayer4_minwidth=10 midlayer4_maxwidth=10 midlayer4_prefwidth=10 minimp=50.000000 maximp=50.000000 favimp=50.000000
Width [All] p2: maxlimit=100 minlimit=4 preferedwidth=15 toplayer_prefwidth=10.8 midlayer1_minwidth=6 midlayer2_minwidth=6 midlayer2_prefwidth=6 midlayer3_minwidth=6 midlayer4_minwidth=6 midlayer5_minwidth=6 midlayer6_minwidth=6 midlayer6_prefwidth=6 bottomlayer_prefwidth=8.7 minimp=50.000000 maximp=50.000000 favimp=50.000000
12 further rules are at their usual default settings.

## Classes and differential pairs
differential pair class 100E: B_RADAR_LVDS_0 B_RADAR_LVDS_1 B_RADAR_LVDS_CLK B_RADAR_LVDS_FRCLK RADAR_LVDS RADAR_LVDS_1 RADAR_LVDS_CLK RADAR_LVDS_FRCLK
differential pair class 90E: D_FTDI_USBD D_XDSET_1
differential pair class 120E: CAN_FD CAN_FD_B
net class POWER: 5V_IN_USB 12V_DC_JACK CONN_5V FTDI_3V3 FTDI_VBUS FTDI_VCORE GND MCU_3V3 MCU_5V PMIC_LS_3V3 PMIC_OUT_1V2 PMIC_OUT_1V8 PMIC_OUT_3V3 REG_1V2 REG_1V8 REG_RF_1V2 USB_5V VCC_3V3 VCC_12V VCC_CAN_3V3 VCC_XDS_3V3 VDDC_1 VSYS_IN
component class PROC182A_XDS110_Interface: C94 C95 C97 C98 C99 C102 C106 C108 C113 C114 C115 C116 C118 C124 C125 C126 C127 R24 R26 R122 R124 R125 R126 R169 R170 R181 R188 R190 R191 R194 R195 R196 R197 R199 R202 R231 R233 R234 R236 R239 R290 S5 U21 U22 Y2
component class PROC182A_USB_PWR_DC_Jack_Switch: C30 C43 C46 C47 C48 C49 C50 C54 C55 C60 C61 C62 C63 C64 C66 C67 C68 C84 C85 C86 D1 D2 D3 D6 D12 J5 J7 L1 L8 L9 ms mx Q2 R1 R4 R9 R20 R23 R27 R33 R35 R36 R72 R73 R74 R75 R172 R174 R179 TP7 TP13 TP14 TP15 U9 U10 U14
component class PROC182A_Temp_Current_sensors_EPROM: C36 C57 C58 C59 C65 C133 R2 R14 R25 R29 R55 R56 R94 R97 R98 R101 R103 R104 R105 R106 R107 R108 R109 R110 R111 R112 R113 R114 R115 R116 R117 R134 R135 R136 R137 R139 R142 R148 R150 R151 R157 R158 R159 R160 R161 R162 R192 R193 R200 R283 U3 U6 U7 U8 U11 U25
component class PROC182A_PMIC: C3 C20 C27 C42 C51 C69 C70 C71 C72 C73 C74 C75 C76 C77 C78 C79 C80 C81 C82 C83 C87 C88 C89 C90 C91 C100 C103 C105 C112 C117 C137 C154 C155 C156 D4 FB1 FB2 FB3 L4 L5 L6 L11 L14 P1 R11 R54 R57 R76 R77 R82 R83 R84 R85 R86 R87 R89 R90 R91 R92 R145 R241 R245 R278 R279 R280 R281 R282 R288 R289 TP16 TP17 TP18 TP19 TP20 TP21 U13 U15 U20
component class PROC182A_MUX_CAN_FD: C107 C109 C110 C111 J8 R127 R128 R129 R130 R131 R132 R133 R140 R143 R144 R147 R149 U18 U19
component class PROC182A_I2C_SPI_Connector: C119 C120 J1 J2 J9 J11 J12 J13 J14 ms R154 R155 R156 R163 R164 R166 R173 R175 R176 R177 R178 R180 R182 R183 R198 R201 R210 R211 R212 R221 R222 R223 R224 R232 R238 R240 R254 R285 R286
component class PROC182A_FTDI: C138 C139 C140 C141 C142 C143 C144 C145 C146 C147 C148 C149 C150 C151 C152 C153 C157 C158 D10 J10 L2 L3 L7 R96 R99 R100 R102 R118 R119 R120 R121 R167 R168 R184 R185 R186 R187 R189 R209 R216 R217 R218 R237 R242 R243 R248 R249 R251 R252 R259 R260 U26 U27 U29 Y3
component class PROC182A_EVM_Hardware: !PCB "CAUTION HOT SURFACE1" FID5 FID6 Logo2 Logo4 ZZ1 ZZ2 ZZ3 ZZ4 ZZ5
component class PROC182A_DCA1000_Connector_Reset: C52 C53 C92 C93 C96 D5 D7 D9 D11 D13 J6 Q1 Q3 Q4 R28 R30 R34 R37 R38 R39 R40 R41 R42 R52 R53 R58 R59 R60 R61 R62 R63 R64 R65 R66 R123 R138 R141 R152 R153 R165 R171 R213 R214 R215 R219 R220 R225 R226 R227 R228 R229 R230 R258 R262 R263 R264 R265 R287 S2 S3 S6 U17
component class PROC182A_CAN_LIN_PHY_Interface: C37 C38 C39 C123 C132 D8 J3 J4 R3 R17 R18 R19 R21 R22 R31 R32 R68 R69 R71 R78 R79 R80 R88 R273 U5 U23
component class PROC182A_Analog_MUX_SPI: C56 C135 C136 R10 R12 R253 R271 R272 R274 R275 TP4 U24 U28 U30
component class PROC182A_Analog_Mux_SOP_Ctrl: C40 C41 C104 R5 R6 R7 R8 R13 R15 R16 R43 R67 R70 R95 R203 R204 R205 R206 R207 R208 R235 R244 R277 S1 S4 S7 S8 TP1 U4 U12 U16
component class Header: J1 J2 J3 J4 J8 J9 J13 P1
component class FiducialMark: FID5 FID6
component class AssemblyNote: ZZ1 ZZ2 ZZ3 ZZ4 ZZ5
component class "PROC182A_Decoupling_caps- QSPI Flash": C1 C2 C4 C5 C6 C7 C8 C9 C10 C11 C12 C13 C14 C15 C16 C17 C18 C19 C21 C22 C24 C25 C26 C34 C35 C44 C45 C121 C128 C130 C131 R44 R45 R46 R47 R48 R49 R50 R51 U2
component class PROC182A_Chip: C31 C32 C33 C134 J15 R81 R93 R146 R246 R247 R250 R255 R256 R257 R261 R267 R268 R269 R270 R276 R284 TP2 TP3 TP5 TP6 TP8 TP9 TP11 TP12 TP22 U1 Y1
net class "TX and RX": RX1 RX2 RX3 RX4 TX1 TX2 TX3 TX4
differential pair B_RADAR_LVDS_0: +NetJ6_56 -NetJ6_58
differential pair B_RADAR_LVDS_1: +NetJ6_50 -NetJ6_52
differential pair B_RADAR_LVDS_CLK: +NetJ6_44 -NetJ6_46
differential pair B_RADAR_LVDS_FRCLK: +NetJ6_26 -NetJ6_28
differential pair RADAR_LVDS_FRCLK: +RADAR_LVDS_FRCLKP -RADAR_LVDS_FRCLKM
differential pair RADAR_LVDS_CLK: +RADAR_LVDS_CLKP -RADAR_LVDS_CLKM
differential pair RADAR_LVDS_1: +RADAR_LVDS_1P -RADAR_LVDS_1M
differential pair RADAR_LVDS: +RADAR_LVDS_0P -RADAR_LVDS_0M
differential pair D_XDSET_1: +XDSET_1_DP -XDSET_1_DM
differential pair D_FTDI_USBD: +FTDI_USBD_P -FTDI_USBD_N
differential pair CAN_FD: +CAN_FD_H -CAN_FD_L
differential pair CAN_FD_B: +CAN_FD_B_H -CAN_FD_B_L

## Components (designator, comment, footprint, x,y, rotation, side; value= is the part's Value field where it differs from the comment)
C1 "GCM155R71C224KE02D" 0402L 1800.26,2296.34 r0 bottom value=0.22uF
C2 "GCM155R71C224KE02D" 0402L 1906.31,2297.64 r0 bottom value=0.22uF
C3 "CGA4J3X7S1A106K125AE" FP-CGA4J3X7S1A106K125AE_0805-MFG 864.17,3184.06 r0 bottom
C4 "GCM155R71C224KE02D" 0402L 1776.8,2561.24 r0 bottom value=0.22uF
C5 "GCM155R71C224KE02D" 0402L 1911.99,2587.64 r0 bottom value=0.22uF
C6 "CGA2B3X7R1H473K050BB" 0402L 1839.55,2550.84 r270 bottom value=0.047uF
C7 "GCM155R71C224KE02D" 0402L 1756.9,2457.59 r90 bottom value=0.22uF
C8 "GCM155R71C224KE02D" 0402L 1738.51,2258.07 r0 bottom value=0.22uF
C9 "GCM188D70E226ME36D" FP-GCM188D70E226ME36D_0603-MFG 2112.42,2537.1 r270 bottom value=22µF
C10 "GCM155R71C224KE02D" 0402L 1973.8,2221.47 r90 bottom value=0.22uF
C11 "GCM155R71C224KE02D" 0402L 1769.15,2622.71 r0 bottom value=0.22uF
C12 "GCM155R71C224KE02D" 0402L 1769.05,2655.89 r0 bottom value=0.22uF
C13 "GCM188D70J106ME36D" FP-GCM188D70J106ME36D_0603-MFG 1759.66,2694.77 r180 bottom
C14 "GCM155R71C224KE02D" 0402L 2031.66,2607.9 r180 bottom value=0.22uF
C15 "GCM188D70J106ME36D" FP-GCM188D70J106ME36D_0603-MFG 2020.87,2647.24 r0 bottom
C16 "GCM155R71C224KE02D" 0402L 1677.2,2499.69 r0 top value=0.22uF
C17 "GRT155C71A225KE13D" FP-GRT155C71A225KE13D_0402-MFG 1735.72,2231.45 r0 top value=2.2µF
C18 "GRT155R70J105KE01D" FP-GRT155R70J105KE01D_0402-MFG 1964.51,2526.3 r180 bottom
C19 "GCM188D70J106ME36D" FP-GCM188D70J106ME36D_0603-MFG 2064.6,2537.48 r270 bottom
C20 "CGA4J3X7S1A106K125AE" FP-CGA4J3X7S1A106K125AE_0805-MFG 2326.31,1432.09 r180 top
C21 "GCM155R71C224KE02D" 0402L 2036.49,2285.27 r270 bottom value=0.22uF
C22 "GRT155R70J105KE01D" FP-GRT155R70J105KE01D_0402-MFG 1915.7,2481.01 r180 bottom
C24 "GCM188D70E226ME36D" FP-GCM188D70E226ME36D_0603-MFG 2054.99,2414.09 r90 bottom value=22µF
C25 "GCM155R71C224KE02D" 0402L 1809.62,2484.01 r90 bottom value=0.22uF
C26 "GCM155R71C224KE02D" 0402L 1740.84,2403.81 r180 bottom value=0.22uF
C27 "CGA4J3X7S1A106K125AE" FP-CGA4J3X7S1A106K125AE_0805-MFG 2490.61,1353.59 r180 top
C30 "EEHZC1V680XP" SM_RADIAL_6.3BMM 1780.39,766.77 r270 top value=68uF
C31 "GCM155R71H104KE02D" 0402 1605.14,2525.48 r270 top value=0.1uF
C32 "GJM1555C1H4R7BB01D" 0402L 2083.65,2735.28 r270 bottom value=4.7pF
C33 "GJM1555C1H4R7BB01D" 0402L 2145.97,2658.54 r180 bottom value=4.7pF
C34 "GCM155R71H104KE02D" 0402 2875.15,1896.26 r180 bottom value=0.1uF
C35 "CL10B105KA8NNNC" 0603 2871.82,1840.59 r0 bottom
C36 "GCM155R71H104KE02D" 0402 2924.66,1786.32 r90 top value=0.1uF
C37 "GCM155R71H104KE02D" 0402 640.72,2058.23 r90 top value=0.1uF
C38 "GCM155R71H104KE02D" 0402 377.8,2191.85 r180 top value=0.1uF
C39 "GCM155R71H472KA37D" 0402L 254.5,1947.48 r0 top value=4700pF
C40 "GCM155R71H104KE02D" 0402 1441.72,1796.4 r270 top value=0.1uF
C41 "GCM155R71H104KE02D" 0402 916.62,2707.58 r0 top value=0.1uF
C42 "GRT155C71A225KE13D" FP-GRT155C71A225KE13D_0402-MFG 2275.14,518.22 r0 top value=2.2µF
C43 "C3216X7R1H475K160AC" 1206_180L 2189.01,1140.06 r0 top value=4.7uF
C44 "GCM188D70E226ME36D" FP-GCM188D70E226ME36D_0603-MFG 2102.78,2414.17 r270 bottom value=22µF
C45 "GCM155R71C224KE02D" 0402L 1703.94,2546.2 r270 bottom value=0.22uF
C46 "GRM155R61A106ME11D" 0402 2595.45,551.55 r0 top value=10uF
C47 "GRM155R61A106ME11D" 0402 2595.45,503.6 r180 top value=10uF
C48 "GCM155R71H104KE02D" 0402 2436.53,1096.88 r90 top value=0.1uF
C49 "C3216X7R1H475K160AC" 1206_180L 1975.79,764.79 r270 top value=4.7uF
C50 "C3216X7R1H475K160AC" 1206_180L 2395.25,715.41 r270 bottom value=4.7uF
C51 "GCM155C71A105KE38D" 0402_070 570.67,2254.41 r0 top value=1uF
C52 "GCM155R71H104KE02D" 0402 1054.8,1902.17 r270 top value=0.1uF
C53 "GCM155R71H104KE02D" 0402 870.17,893.61 r0 top value=0.1uF
C54 "CL10B105KA8NNNC" 0603 2052.5,762.29 r270 top
C55 "GRM31CR61A476KE15L" 1206_180 2490.16,595.47 r270 top value=47uF
C56 "GCM155R71H104KE02D" 0402 2743.06,1725.45 r0 top value=0.1uF
C57 "GCM155R71H104KE02D" 0402 1159.29,3312.54 r90 bottom value=0.1uF
C58 "GCM155R71H104KE02D" 0402 1025.06,2750.58 r90 bottom value=0.1uF
C59 "GCM155R71H104KE02D" 0402 2121.92,1813.73 r90 top value=0.1uF
C60 "GCM155R71H104KE02D" 0402 2113.78,764.29 r270 top value=0.1uF
C61 "GCM155R71H104KE02D" 0402 2330.57,716.22 r270 bottom value=0.1uF
C62 "CL10B105KA8NNNC" 0603 2181.01,689.78 r0 bottom
C63 "GCM155R71H104KE02D" 0402 2381.72,1096.88 r90 top value=0.1uF
C64 "C1206C106J3RACAUTO" 1206_180 2174.63,785.87 r0 bottom value=10uF
C65 "GCM155R71H104KE02D" 0402 292,2468.79 r180 top value=0.1uF
C66 "GCM155C71A105KE38D" 0402_070 2376.19,752.87 r270 top value=1uF
C67 "GCM155R71H104KE02D" 0402 2329.83,752.86 r90 top value=0.1uF
C68 "GCM155C71A105KE38D" 0402_070 2250.06,630.03 r270 top value=1uF
C69 "GCM155R71H104KE02D" 0402 1577.79,1304.85 r0 top value=0.1uF
C70 "GRM31CR70J226ME19K" FP-GRM31CR70J226ME19K_1206-MFG 1350.64,1357.76 r90 top value=22µF
C71 "GRM31CR70J226ME19K" FP-GRM31CR70J226ME19K_1206-MFG 1259.76,1353.83 r90 top value=22µF
C72 "GRM31CR60J476ME19L" 1206_180 1211.7,1488.07 r180 top value=47uF
C73 "CL10B105KA8NNNC" 0603 1520.59,1444.71 r180 top
C74 "C3216X7R1H475K160AC" 1206_180L 1716.09,1179.04 r0 top value=4.7uF
C75 "CGA4J3X7S1A106K125AE" FP-CGA4J3X7S1A106K125AE_0805-MFG 1490.48,1351.21 r270 top
C76 "CGA4J3X7S1A106K125AE" FP-CGA4J3X7S1A106K125AE_0805-MFG 1963.25,1344.37 r90 top
C77 "CGA4J3X7S1A106K125AE" FP-CGA4J3X7S1A106K125AE_0805-MFG 1791.73,1507.45 r270 top
C78 "CGA4J3X7S1A106K125AE" FP-CGA4J3X7S1A106K125AE_0805-MFG 1787.69,1315.9 r90 top
C79 "GRT155C71A225KE13D" FP-GRT155C71A225KE13D_0402-MFG 1619.02,1475.87 r180 bottom value=2.2µF
C80 "GRM31CR70J226ME19K" FP-GRM31CR70J226ME19K_1206-MFG 680.59,3316.93 r90 bottom value=22µF
C81 "GRM31CR70J226ME19K" FP-GRM31CR70J226ME19K_1206-MFG 764.89,3316.93 r90 bottom value=22µF
C82 "GRM31CR60J476ME19L" 1206_180 853.96,3106.86 r0 bottom value=47uF
C83 "CGA4J3X7S1A106K125AE" FP-CGA4J3X7S1A106K125AE_0805-MFG 1969.16,1512.19 r270 top
C84 "GCM155C71A474KE36D" 0402L 2595.89,463.94 r180 top value=0.47uF
C85 "GCM155R71C224KE02D" 0402L 2596.31,427.4 r0 top value=0.22uF
C86 "GRT188R61A106KE13D" 0603S 2937.09,137.95 r90 top value=10uF
C87 "GRT155C71A225KE13D" FP-GRT155C71A225KE13D_0402-MFG 1581.68,1503.69 r180 top value=2.2µF
C88 "CL10B105KA8NNNC" 0603 1614.42,1308.62 r0 bottom
C89 "GRM31CR70J226ME19K" FP-GRM31CR70J226ME19K_1206-MFG 2111.24,1350.55 r90 top value=22µF
C90 "GRM31CR70J226ME19K" FP-GRM31CR70J226ME19K_1206-MFG 2189.62,1352.95 r90 top value=22µF
C91 "GRM31CR70J226ME19K" FP-GRM31CR70J226ME19K_1206-MFG 2318.13,1505.98 r180 top value=22µF
C92 "GCM155C71A474KE36D" 0402L 1919.67,642.68 r90 bottom value=0.47uF
C93 "GCM155C71A105KE38D" 0402_070 1880.85,641.98 r90 bottom value=1uF
C94 "GCM155R71H104KE02D" 0402 1639.64,1634.65 r270 bottom value=0.1uF
C95 "GCM155R71H104KE02D" 0402 1663.56,2183.52 r270 bottom value=0.1uF
C96 "GRT188R61A106KE13D" 0603S 1837.59,650.16 r270 bottom value=10uF
C97 "CC0402DRNPO9BN8R0" 0402L 1681.09,1771.62 r90 bottom value=8pF
C98 "CC0402DRNPO9BN8R0" 0402L 1681.09,1852.82 r270 bottom value=8pF
C99 "GCM155R71H104KE02D" 0402 853.37,1492.45 r0 bottom value=0.1uF
C100 "CL10B105KA8NNNC" 0603 1737.26,1463.05 r180 bottom
C102 "GCM155R71E103KA37D" 0402L 857.31,1537.45 r0 bottom value=0.01uF
C103 "GRM31CR60J476ME19L" 1206_180 2498.24,1270.49 r180 top value=47uF
C104 "GCM155R71H104KE02D" 0402 1137.8,2016.73 r90 top value=0.1uF
C105 "GRT155C71A225KE13D" FP-GRT155C71A225KE13D_0402-MFG 2186.43,459.33 r270 top value=2.2µF
C106 "GCM155R71H104KE02D" 0402 897.91,2114.19 r0 bottom value=0.1uF
C107 "GCM155R71H104KE02D" 0402 1223.43,2886.81 r90 top value=0.1uF
C108 "GCM155C71A105KE38D" 0402_070 1431.68,1690.92 r180 top value=1uF
C109 "GCM155R71H104KE02D" 0402 377.63,1780.14 r0 top value=0.1uF
C110 "GCM155R71H104KE02D" 0402 640.55,1646.52 r90 top value=0.1uF
C111 "GCM155R71H472KA37D" 0402L 254.33,1535.77 r0 top value=4700pF
C112 "GRT155C71A225KE13D" FP-GRT155C71A225KE13D_0402-MFG 358.31,2273.11 r270 top value=2.2µF
C113 "GCM155R71H104KE02D" 0402 1294.66,2322.53 r270 bottom value=0.1uF
C114 "GCM155C71A105KE38D" 0402_070 1658,1999.25 r270 bottom value=1uF
C115 "GCM155R71E103KA37D" 0402L 923.42,1817.76 r90 bottom value=0.01uF
C116 "GCM155R71H104KE02D" 0402 913.07,1954.87 r270 bottom value=0.1uF
C117 "CGA4J3X7S1A106K125AE" FP-CGA4J3X7S1A106K125AE_0805-MFG 1424.98,1350.58 r270 top
C118 "GCM155R71E103KA37D" 0402L 903.11,1693.47 r0 bottom value=0.01uF
C119 "GCM155C71A474KE36D" 0402L 387.32,2074.14 r0 bottom value=0.47uF
C120 "GCM155C71A474KE36D" 0402L 662.6,1968.97 r270 bottom value=0.47uF
C121 "GCM155R71C224KE02D" 0402L 2018.67,2345.93 r180 bottom value=0.22uF
C123 "GCM155R71H104KE02D" 0402 393.53,937.13 r0 top value=0.1uF
C124 "GRT155C71A225KE13D" FP-GRT155C71A225KE13D_0402-MFG 1724.62,1929.29 r0 bottom value=2.2µF
C125 "GCM155R71H104KE02D" 0402 1729.25,1972.41 r180 bottom value=0.1uF
C126 "GCM155R71H104KE02D" 0402 1169.76,1560.6 r0 bottom value=0.1uF
C127 "GCM155C71A105KE38D" 0402_070 1250.8,1570.32 r0 bottom value=1uF
C128 "GCM155R71E103KA37D" 0402L 1968.32,2312.7 r270 bottom value=0.01uF
C130 "GCM155R71E103KA37D" 0402L 1959.17,2463.31 r90 bottom value=0.01uF
C131 "GCJ21BR71C475KA01L" FP-GCJ21BR71C475KA01L_0805-MFG 1895.29,2248.61 r0 bottom value=4.7µF
C132 "885012005063" 0402 256.77,812.7 r270 top value=220pF
C133 "GCM155R71H104KE02D" 0402 2451.49,1642.77 r90 top value=0.1uF
C134 "GCM155R71C224KE02D" 0402L 1538.84,2451.53 r0 top value=0.22uF
C135 "GCM155R71H104KE02D" 0402 570.67,3194.63 r90 top value=0.1uF
C136 "GCM155R71H104KE02D" 0402 292.04,3057.1 r180 top value=0.1uF
C137 "C3216X7R1H475K160AC" 1206_180L 1717.3,1095.17 r0 top value=4.7uF
C138 "GCM155R71H104KE02D" 0402 1660.54,524.74 r0 bottom value=0.1uF
C139 "C1608X7S1A475K080AC" 0603L 959.67,682.42 r270 bottom value=4.7uF
C140 "GCM155R71H104KE02D" 0402 821.09,1121.98 r90 bottom value=0.1uF
C141 "C1608X7S1A475K080AC" 0603L 752.28,961.23 r90 bottom value=4.7uF
C142 "GCM155R71H104KE02D" 0402 802.28,957.29 r270 bottom value=0.1uF
C143 "GCM155R71H104KE02D" 0402 1362.09,788.5 r0 bottom value=0.1uF
C144 "GCM155R71H104KE02D" 0402 1362.25,740.07 r0 bottom value=0.1uF
C145 "C1608X7S1A475K080AC" 0603L 744.11,1094.58 r180 bottom value=4.7uF
C146 "GCM155R71H104KE02D" 0402 777.96,1044.27 r0 bottom value=0.1uF
C147 "GCM1555C1H8R0DA16D" 0402L 771.06,803.24 r180 bottom
C148 "GCM1555C1H8R0DA16D" 0402L 861.57,803.24 r0 bottom
C149 "CL10B105KA8NNNC" 0603 1227.92,656.45 r0 bottom
C150 "GCM155R71H104KE02D" 0402 1218.7,711.79 r180 bottom value=0.1uF
C151 "CL10B105KA8NNNC" 0603 1437.38,978.77 r180 bottom
C152 "GCM155R71H104KE02D" 0402 1252.76,1339.18 r90 bottom value=0.1uF
C153 "GCM155R71H104KE02D" 0402 1077.44,1328.2 r0 bottom value=0.1uF
C154 "GCM155R71H104KE02D" 0402 1697.59,1266.89 r180 top value=0.1uF
C155 "CGA4J3X7S1A106K125AE" FP-CGA4J3X7S1A106K125AE_0805-MFG 2048.34,1511.16 r90 top
C156 "CGA4J3X7S1A106K125AE" FP-CGA4J3X7S1A106K125AE_0805-MFG 2038.28,1343.58 r270 top
C157 "GRT188R61A106KE13D" 0603S 2927.45,1550.77 r90 top value=10uF
C158 "GCM155R71H104KE02D" 0402 2791.91,1635.41 r180 top value=0.1uF
"CAUTION HOT SURFACE1" "CAUTION HOT SURFACE" IEC_HotSurface_Small 1862.21,1128.94 r180 bottom
D1 "PMEG3020EP,115" SOD-128 2745.09,324.55 r270 top value=30V
D2 "PMEG3050EP,115" SOD-128 2222.08,1031.83 r0 top value=30V
D3 "TLMY1100-GS15" FP-TLMY1100-GS15_0603-MFG 1586.04,934.47 r0 top
D4 "SMS3923-040LF" SOD-882 1310.79,1148.5 r180 top value=V
D5 "TLMY1100-GS15" FP-TLMY1100-GS15_0603-MFG 1315.98,600.82 r180 top
D6 "TLMY1100-GS15" FP-TLMY1100-GS15_0603-MFG 1864.17,491.14 r180 top
D7 "TLMY1100-GS15" FP-TLMY1100-GS15_0603-MFG 977.3,439.55 r180 top
D8 "PMEG3020EP,115" SOD-128 351.36,808.26 r0 bottom value=30V
D9 "TLMY1100-GS15" FP-TLMY1100-GS15_0603-MFG 454.57,2729.64 r0 top
D10 "TLMY1100-GS15" FP-TLMY1100-GS15_0603-MFG 1567.26,1033.48 r0 top
D11 "TLMY1100-GS15" FP-TLMY1100-GS15_0603-MFG 2078.74,474.41 r180 top
D12 "PMEG3020EP,115" SOD-128 2805.8,1371.65 r90 top value=30V
D13 "TLMY1100-GS15" FP-TLMY1100-GS15_0603-MFG 725.38,884.63 r180 top
Designator6_2 "Comment" BRAKE_WAY_HOLES1X3_CUST 252.56,-39.37 r0 top
Designator6_3 "Comment" BRAKE_WAY_HOLES1X3_CUST 2915.75,-39.37 r180 bottom
Designator6_4 "Comment" BRAKE_WAY_HOLES1X3_CUST 252.56,3740.16 r0 bottom
Designator6_5 "Comment" BRAKE_WAY_HOLES1X3_CUST 1899.55,-39.37 r180 bottom
Designator6_6 "Comment" BRAKE_WAY_HOLES1X3_CUST 957.69,-39.37 r0 top
Designator6_7 "Comment" BRAKE_WAY_HOLES1X3_CUST 2915.75,3740.16 r180 top
Designator6_8 "Comment" BRAKE_WAY_HOLES1X3_CUST 1069.27,3740.16 r0 bottom
Designator6_9 "Comment" BRAKE_WAY_HOLES1X3_CUST 2099.04,3740.16 r180 top
FB1 "MPZ2012S300ATD25" FP-MPZ2012S300ATD25_0805-MFG 865.16,3258.86 r0 bottom
FB2 "MPZ2012S300ATD25" FP-MPZ2012S300ATD25_0805-MFG 2262.37,1343.71 r90 top
FB3 "MPZ2012S300ATD25" FP-MPZ2012S300ATD25_0805-MFG 2347,1304.03 r0 top
FID5 "Fiducial" FIDUCIAL10-20 741.09,3609.47 r90 top
FID6 "Fiducial" FIDUCIAL10-20 2922.27,460.19 r90 top
FID7 "Fiducial" FIDUCIAL10-20 53.96,460.19 r90 top
FID8 "Fiducial" FIDUCIAL10-20 2922.27,460.19 r0 bottom
FID9 "Fiducial" FIDUCIAL10-20 53.96,460.19 r0 bottom
FID10 "Fiducial" FIDUCIAL10-20 741.09,3609.47 r0 bottom
FID11 "Fiducial" FIDUCIAL10-20 350,3905.13 r90 top
FID12 "Fiducial" FIDUCIAL10-20 2818.31,3905.13 r270 top
FID13 "Fiducial" FIDUCIAL10-20 2818.31,-204.34 r270 top
FID14 "Fiducial" FIDUCIAL10-20 350,-204.34 r90 top
FID15 "Fiducial" FIDUCIAL10-20 350,3905.13 r0 bottom
FID16 "Fiducial" FIDUCIAL10-20 2818.31,3905.13 r0 bottom
FID17 "Fiducial" FIDUCIAL10-20 2818.31,-204.34 r0 bottom
FID18 "Fiducial" FIDUCIAL10-20 350,-204.34 r0 bottom
J1 "61300311021" Wurth_61300311021 158.07,2469.5 r270 top locked
J2 "PBC07SAAN" Sullins_xxC07SAAN 654.92,119.45 r180 top
J3 "61300311021" Wurth_61300311021 158.23,2051.41 r270 top locked
J4 "61300411021" Wurth_61300411021 158.07,984.5 r270 top locked
J5 "105017-0001" CONN_105017-0001 3058.36,266.35 r90 top locked
J6 "QSH-030-01-L-D-A" Samtec_QSH-030-01-X-D-A 2251.82,457.65 r270 bottom locked
J7 "PJ-063AH" CUI_PJ-063AH 2873.27,757.12 r0 top locked
J8 "61300311021" Wurth_61300311021 158.07,1639.71 r270 top locked
J9 "61300311121" WURTH_61300311121 721.75,1423.37 r270 top
J10 "105017-0001" CONN_105017-0001 3058.07,1668.38 r90 top locked
J11 "SSM-110-S-DV" Samtec_SSM-110-x-DV 470.78,1547.45 r270 bottom locked
J12 "SSM-110-S-DV" Samtec_SSM-110-x-DV 2170.78,1547.45 r270 bottom locked
J13 "61300311121" WURTH_61300311121 779.43,2267.59 r0 top
J14 "0022288072" FP-0022288072_HDR7-MFG 49.02,3065.75 r90 top locked
J15 "SOLDER JUMPER" SolderJumper 506.88,1369.43 r180 top
L1 "XGL5050-472MEC" FP-XGL5050-472MEC_SMT2_5MM28_5MM48-MFG 1969.04,1031.62 r270 top value=4.7uH
L2 "BLM15HG601SN1D" 0402L 712.28,953.35 r270 bottom value="600 ohm"
L3 "BLM15HG601SN1D" 0402L 770.99,1158.91 r270 bottom value="600 ohm"
L4 "LQM2MPZR10MJHL" "FP-LQM2MPZR10MJHL_0806 (2016)-MFG" 1166.24,1382.89 r90 top value=0.1uH
L5 "TFM252012ALVA1R5MTAA" FP-TFM252012ALVA1R5MTAA_1008-MFG 1545.69,1233.05 r180 top value=1.5uH
L6 "TFM201610ALMAR47MTAA" TFM201610ALMA 1880.83,1331.97 r270 top value=470nH
L7 "BLM15HG601SN1D" 0402L 1313.51,662.98 r270 bottom value="600 ohm"
L8 "BLM21PG300SH1D" 0805 2825.28,1536.6 r180 top value="30 ohm"
L9 "BLM21PG300SH1D" 0805 2824.58,166.55 r180 top value="30 ohm"
L11 "TFM201610ALMAR47MTAA" TFM201610ALMA 1878.93,1499.87 r90 top value=470nH
L14 "BLM15PD300SZ1D" 0402L 1578.07,1542.75 r180 top
Logo2 "CE Mark" CE_Mark_5mm 2055.7,170.45 r0 top
Logo4 "WEEE logo" WEEE_Minimum 482.9,2640.95 r180 bottom
P1 "TSW-102-07-G-S" TSW-102-07-G-S 272.13,2304.41 r270 top
Q1 "SSM3K35AMFV,L3F" FP-SSM3K35AMFV,L3F_SOT-723-MFG 1397.16,600.82 r180 top
Q2 "BSS123W-7-F" SOT-323 1557.5,857.07 r90 top value=100V
Q3 "SSM3K35AMFV,L3F" FP-SSM3K35AMFV,L3F_SOT-723-MFG 2107.12,413.98 r90 top
Q4 "SSM3K35AMFV,L3F" FP-SSM3K35AMFV,L3F_SOT-723-MFG 1058.48,439.55 r180 top
R1 "MCT06030Z0000ZP500" 0603 2884.94,336.42 r180 top value=0
R2 "CRCW040210K0FKED" 0402L 967.14,3412.97 r180 bottom value=10.0k
R3 "ERJ-2GE0R00X" FP-ERJ-2GE0R00X_0402-MFG 404.36,1881.85 r180 top value=0
R4 "CRCW040262K0JNED" 0402 2213.72,900.92 r90 top value=62k
R5 "CRCW040210K0FKED" 0402L 1487.66,1812.09 r270 top value=10.0k
R6 "RC0402FR-074K7L" 0402 1360.24,1826.77 r90 top value=4.70k
R7 "CRCW040210K0FKED" 0402L 771.91,2707.74 r0 top value=10.0k
R8 "CRCW040210K0FKED" 0402L 960.27,2346.78 r0 top value=10.0k
R9 "CRCW040210K0FKED" 0402L 2163.93,897.38 r270 top value=10.0k
R10 "CRCW040210K0FKED" 0402L 2620.96,1392.92 r270 bottom value=10.0k
R11 "CRCW0402100KFKED" 0402 2379.68,406.53 r90 top value=100k
R12 "CRCW040210K0FKED" 0402L 2478.87,1418.15 r0 bottom value=10.0k
R13 "CRCW0402750RFKED" 0402L 276.26,653.31 r180 top value=750
R14 "CRCW040210K0FKED" 0402L 1031.09,3545.23 r90 bottom value=10.0k
R15 "ERJ-2GE0R00X" FP-ERJ-2GE0R00X_0402-MFG 870.34,482.56 r90 top value=0
R16 "CRCW0402750RFKED" 0402L 810.66,422.39 r180 top value=750
R17 "CRCW040210K0FKED" 0402L 498.82,810.73 r0 top value=10.0k
R18 "ERJ-2GE0R00X" FP-ERJ-2GE0R00X_0402-MFG 476.37,744.34 r180 top value=0
R19 "ERJ-2GE0R00X" FP-ERJ-2GE0R00X_0402-MFG 479.31,861.92 r180 top value=0
R20 "RC0402FR-074K7L" 0402 2213.57,900.8 r270 bottom value=4.70k
R21 "ERJ-2RKF1001X" 0402 281.69,934.5 r0 top value=1.00k
R22 "CRCW040210K0FKED" 0402L 477.36,709.34 r180 top value=10.0k
R23 "RC0402FR-074K7L" 0402 2163.93,901.32 r270 bottom value=4.70k
R24 "ERJ-2GE0R00X" FP-ERJ-2GE0R00X_0402-MFG 966.13,2319.7 r270 bottom value=0
R25 "ERJ-2GE0R00X" FP-ERJ-2GE0R00X_0402-MFG 1167.22,3403.4 r0 bottom value=0
R26 "ERJ-2GE0R00X" FP-ERJ-2GE0R00X_0402-MFG 798.72,2083.94 r180 bottom value=0
R27 "CRCW040210K0FKED" 0402L 2136.59,651.13 r0 top value=10.0k
R28 "ERJ-2GEJ511X" 0402L 988.19,355.32 r270 top value=510
R29 "ERJ-2GE0R00X" FP-ERJ-2GE0R00X_0402-MFG 1106.66,3545.47 r90 bottom value=0
R30 "MCT06030Z0000ZP500" 0603 1751.69,625.93 r0 bottom value=0
R31 "MCT06030Z0000ZP500" 0603 274.56,1134.5 r0 top value=0
R32 "MCT06030Z0000ZP500" 0603 274.56,1034.5 r0 top value=0
R33 "CRCW040221K5FKED" 0402 2205.06,633.65 r90 top value=21.5k
R34 "ERJ-2GE0R00X" FP-ERJ-2GE0R00X_0402-MFG 1935.61,270.03 r180 bottom value=0
R35 "CRCW040223K7FKED" 0402 2263.21,901.32 r90 bottom value=23.7k
R36 "RT0603BRD0712K1L" 0603 2359.87,881.48 r0 top value=12.1k
R37 "ERJ-2GE0R00X" FP-ERJ-2GE0R00X_0402-MFG 1912.63,753.46 r270 bottom value=0
R38 "ERJ-2GE0R00X" FP-ERJ-2GE0R00X_0402-MFG 1935.01,235.06 r180 bottom value=0
R39 "ERJ-2GE0R00X" FP-ERJ-2GE0R00X_0402-MFG 1949.84,752.57 r270 bottom value=0
R40 "ERJ-2GE0R00X" FP-ERJ-2GE0R00X_0402-MFG 2025.44,239.67 r270 bottom value=0
R41 "ERJ-2GE0R00X" FP-ERJ-2GE0R00X_0402-MFG 1986.6,752.57 r270 bottom value=0
R42 "ERJ-2GE0R00X" FP-ERJ-2GE0R00X_0402-MFG 2115.88,235.06 r0 bottom value=0
R43 "ERJ-2GE0R00X" FP-ERJ-2GE0R00X_0402-MFG 366.12,653.31 r180 top value=0
R44 "CRCW040210K0FKED" 0402 2559.06,2102.59 r180 bottom value=10.0k
R45 "CRCW040233R2FKED" 0402 2963.3,2126.21 r90 bottom value=33.2
R46 "CRCW040233R2FKED" 0402 2606.7,1993.38 r0 bottom value=33.2
R47 "CRCW040233R2FKED" 0402 2606.3,2052.59 r0 bottom value=33.2
R48 "CRCW040233R2FKED" 0402 2986.92,2052.59 r0 bottom value=33.2
R49 "CRCW040210K0FKED" 0402 3009.77,1918.97 r270 bottom value=10.0k
R50 "RC0402FR-1047K5L" FP-RC0402FR-1047K5L_0402-MFG 2629.46,1952.59 r0 bottom value=47.5k
R51 "CRCW040233R2FKED" 0402 2986.15,2002.59 r0 bottom value=33.2
R52 "ERJ-2GE0R00X" FP-ERJ-2GE0R00X_0402-MFG 2021.6,753.02 r270 bottom value=0
R53 "ERJ-2GE0R00X" FP-ERJ-2GE0R00X_0402-MFG 2115.28,270.03 r0 bottom value=0
R54 "CRCW040210K0FKED" 0402L 1581.55,1696.86 r90 top value=10.0k
R55 "ERJ-2GE0R00X" FP-ERJ-2GE0R00X_0402-MFG 2750.48,1767.34 r180 top value=0
R56 "ERJ-2GE0R00X" FP-ERJ-2GE0R00X_0402-MFG 2749.88,1807.94 r180 top value=0
R57 "CRCW040210K0FKED" 0402L 1546.55,1697.86 r270 top value=10.0k
R58 "ERJ-2GE0R00X" FP-ERJ-2GE0R00X_0402-MFG 2055.7,751.49 r270 bottom value=0
R59 "ERJ-2GE0R00X" FP-ERJ-2GE0R00X_0402-MFG 2458.51,796.85 r270 bottom value=0
R60 "ERJ-2GE0R00X" FP-ERJ-2GE0R00X_0402-MFG 2493.18,796.85 r270 bottom value=0
R61 "ERJ-2GE0R00X" FP-ERJ-2GE0R00X_0402-MFG 2532.48,800.2 r270 bottom value=0
R62 "ERJ-2GE0R00X" FP-ERJ-2GE0R00X_0402-MFG 2561.82,702.25 r270 bottom value=0
R63 "ERJ-2GE0R00X" FP-ERJ-2GE0R00X_0402-MFG 2604.83,630.51 r180 bottom value=0
R64 "ERJ-2GEJ511X" 0402L 537.8,2729.64 r0 top value=510
R65 "CRCW040210K0FKED" 0402L 445.71,2769.64 r180 top value=10.0k
R66 "ERJ-2GEJ511X" 0402L 1130.8,423.81 r0 top value=510
R67 "ERJ-2GE0R00X" FP-ERJ-2GE0R00X_0402-MFG 870.97,386.19 r180 top value=0
R68 "CRCW040261R9FKED" 0402L 274.18,2012.17 r90 top value=61.9
R69 "ERJ-2GE0R00X" FP-ERJ-2GE0R00X_0402-MFG 710.89,2081.85 r0 top value=0
R70 "ERJ-2RKF1001X" 0402 1078.42,1046.11 r180 top value=1.00k
R71 "CRCW040210K0FKED" 0402L 354.18,1902.17 r90 top value=10.0k
R72 "CRCW040210K0FKED" 0402L 2901.31,336.63 r180 bottom value=10.0k
R73 "CRCW040210K0FKED" 0402L 2136.26,688.47 r180 top value=10.0k
R74 "RC0402FR-074K7L" 0402 2263.39,900.92 r270 top value=4.70k
R75 "RC0402FR-074K7L" 0402 2351.31,881.32 r180 bottom value=4.70k
R76 "ERJ-2RKF1001X" 0402 1737.64,1657.63 r270 top value=1.00k
R77 "ERJ-2GE0R00X" FP-ERJ-2GE0R00X_0402-MFG 1683.59,1594.79 r0 top value=0
R78 "ERJ-2GE0R00X" FP-ERJ-2GE0R00X_0402-MFG 506.98,1929.49 r180 top value=0
R79 "CRCW040261R9FKED" 0402L 274.18,2101.54 r90 top value=61.9
R80 "ERJ-2GE0R00X" FP-ERJ-2GE0R00X_0402-MFG 640.89,2131.85 r180 top value=0
R81 "ERJ-2GE0R00X" FP-ERJ-2GE0R00X_0402-MFG 2289.48,2207.46 r0 top value=0
R82 "CRCW040210K0FKED" 0402L 575.36,2369.21 r0 top value=10.0k
R83 "ERJ-2GE0R00X" FP-ERJ-2GE0R00X_0402-MFG 1740.44,1556.73 r270 top value=0
R84 "CRCW04021K96FKED" 0402 1802.95,1655.17 r270 top value=1.96k
R85 "ERJ-2GE0R00X" FP-ERJ-2GE0R00X_0402-MFG 1561.32,1588.12 r0 top value=0
R86 "CRCW040210K0FKED" 0402L 555.67,2309.53 r90 top value=10.0k
R87 "CRCW040210R2FKED" 0402 1410.96,1147.76 r180 top value=10.2
R88 "ERJ-2GE0R00X" FP-ERJ-2GE0R00X_0402-MFG 499.31,778.73 r180 top value=0
R89 "ERJ-2GE0R00X" FP-ERJ-2GE0R00X_0402-MFG 1591.83,1526.47 r0 bottom value=0
R90 "ERJ-2GE0R00X" FP-ERJ-2GE0R00X_0402-MFG 1719.96,1560.01 r180 bottom value=0
R91 "ERJ-2GE0R00X" FP-ERJ-2GE0R00X_0402-MFG 2304.99,309.8 r180 top value=0
R92 "CRCW0402100KFKED" 0402 2301.55,349.8 r0 top value=100k
R93 "CRCW040233R2FKED" 0402 1530.38,2374.99 r0 top value=33.2
R94 "CRCW040210K0FKED" 0402L 1070.46,3545.23 r270 bottom value=10.0k
R95 "CRCW040210K0FKED" 0402L 1236.83,2026.17 r180 top value=10.0k
R96 "ERJ-2GE0R00X" FP-ERJ-2GE0R00X_0402-MFG 1070.78,1155.7 r180 top value=0
R97 "CRCW040210K0FKED" 0402L 254.77,2549.1 r270 top value=10.0k
R98 "CRCW040210K0FKED" 0402L 254.77,2638.01 r90 top value=10.0k
R99 "CRCW0402100KFKED" 0402 1161.06,1387.6 r270 bottom value=100k
R100 "ERJ-2GE0R00X" FP-ERJ-2GE0R00X_0402-MFG 1156.74,1122.22 r270 top value=0
R101 "CRCW040210K0FKED" 0402L 967.14,3372.97 r0 bottom value=10.0k
R102 "ERJ-2GE0R00X" FP-ERJ-2GE0R00X_0402-MFG 1211.13,1131.76 r180 top value=0
R103 "CRCW040210K0FKED" 0402L 991.09,3545.23 r270 bottom value=10.0k
R104 "CRCW040210K0FKED" 0402L 832.74,2811.18 r180 bottom value=10.0k
R105 "CRCW040210K0FKED" 0402L 896.69,2983.45 r90 bottom value=10.0k
R106 "CRCW040210K0FKED" 0402L 2317.92,1909.92 r0 top value=10.0k
R107 "CRCW040210K0FKED" 0402L 2253.97,2042.18 r90 top value=10.0k
R108 "ERJ-2GE0R00X" FP-ERJ-2GE0R00X_0402-MFG 1032.81,2841.61 r0 bottom value=0
R109 "ERJ-2GE0R00X" FP-ERJ-2GE0R00X_0402-MFG 2117.85,1900.35 r180 top value=0
R110 "ERJ-2GE0R00X" FP-ERJ-2GE0R00X_0402-MFG 972.26,2983.68 r90 bottom value=0
R111 "ERJ-2GE0R00X" FP-ERJ-2GE0R00X_0402-MFG 2178.41,2042.41 r90 top value=0
R112 "CRCW040210K0FKED" 0402L 936.06,2983.45 r270 bottom value=10.0k
R113 "CRCW040210K0FKED" 0402L 832.74,2851.18 r0 bottom value=10.0k
R114 "CRCW040210K0FKED" 0402L 856.69,2983.45 r270 bottom value=10.0k
R115 "CRCW040210K0FKED" 0402L 2214.6,2042.18 r270 top value=10.0k
R116 "CRCW040210K0FKED" 0402L 2317.92,1869.92 r180 top value=10.0k
R117 "CRCW040210K0FKED" 0402L 2293.97,2042.18 r270 top value=10.0k
R118 "ERJ-2GE0R00X" FP-ERJ-2GE0R00X_0402-MFG 1215.55,1067.91 r180 top value=0
R119 "ERJ-2GE0R00X" FP-ERJ-2GE0R00X_0402-MFG 1292.63,1058.76 r90 top value=0
R120 "ERJ-2GE0R00X" FP-ERJ-2GE0R00X_0402-MFG 1406.06,860.66 r0 bottom value=0
R121 "ERJ-2GE0R00X" FP-ERJ-2GE0R00X_0402-MFG 1147.74,677.94 r270 bottom value=0
R122 "CRCW040233R2FKED" 0402 1035.35,2348.66 r90 bottom value=33.2
R123 "CRCW040210K0FKED" 0402L 1028.35,1711.08 r270 top value=10.0k
R124 "CRCW040233R2FKED" 0402 1085.33,2348.66 r90 bottom value=33.2
R125 "CRCW040233R2FKED" 0402 1135.31,2331.42 r90 bottom value=33.2
R126 "CRCW040233R2FKED" 0402 1208.2,2335.24 r90 bottom value=33.2
R127 "CRCW040210K0FKED" 0402L 1101.05,2832.5 r180 top value=10.0k
R128 "CRCW040210K0FKED" 0402L 1306.31,2460.72 r270 top value=10.0k
R129 "ERJ-2GE0R00X" FP-ERJ-2GE0R00X_0402-MFG 710.73,1670.14 r0 top value=0
R130 "CRCW040261R9FKED" 0402L 274.01,1600.46 r90 top value=61.9
R131 "ERJ-2GE0R00X" FP-ERJ-2GE0R00X_0402-MFG 404.19,1510.14 r180 top value=0
R132 "ERJ-2GE0R00X" FP-ERJ-2GE0R00X_0402-MFG 506.81,1517.78 r180 top value=0
R133 "ERJ-2GE0R00X" FP-ERJ-2GE0R00X_0402-MFG 404.19,1470.14 r180 top value=0
R134 "WSL1206R0100FEB" FP-WSL1206R0100FEB_1206-MFG 2565.34,1524.68 r180 top value=10m
R135 "CRCW040210K0FKED" 0402L 2646.78,1699.68 r0 top value=10.0k
R136 "CRCW040210K0FKED" 0402L 2582.83,1871.94 r90 top value=10.0k
R137 "ERJ-2GE0R00X" FP-ERJ-2GE0R00X_0402-MFG 2446.7,1730.11 r180 top value=0
R138 "CRCW040210K0FKED" 0402L 1081.26,1711.08 r270 top value=10.0k
R139 "ERJ-2GE0R00X" FP-ERJ-2GE0R00X_0402-MFG 2507.26,1872.17 r90 top value=0
R140 "CRCW040261R9FKED" 0402L 274.01,1689.83 r90 top value=61.9
R141 "ERJ-2GEJ511X" 0402L 1227.75,600.82 r180 top value=510
R142 "CRCW040210K0FKED" 0402L 2543.66,1872.15 r270 top value=10.0k
R143 "ERJ-2GE0R00X" FP-ERJ-2GE0R00X_0402-MFG 640.73,1720.14 r180 top value=0
R144 "CRCW040210K0FKED" 0402L 354.01,1490.46 r90 top value=10.0k
R145 "RC0402FR-074K7L" 0402 1713.97,1241.67 r270 bottom value=4.70k
R146 "CRCW0402100KFKED" 0402L 1665.22,2161.05 r0 top value=100k
R147 "CRCW0402100KFKED" 0402L 1266.78,2460.14 r90 top value=100k
R148 "CRCW040210K0FKED" 0402L 2646.77,1739.68 r180 top value=10.0k
R149 "CRCW0402100KFKED" 0402L 1303.75,2847.79 r180 top value=100k
R150 "CRCW040210K0FKED" 0402L 2622.83,1871.94 r270 top value=10.0k
R151 "CRCW040210K0FKED" 0402L 2757.43,1862.51 r270 top value=10.0k
R152 "ERJ-2GE0R00X" FP-ERJ-2GE0R00X_0402-MFG 2563.98,800.69 r90 bottom value=0
R153 "ERJ-2GE0R00X" FP-ERJ-2GE0R00X_0402-MFG 2594.47,702.25 r90 bottom value=0
R154 "MCT06030Z0000ZP500" 0603 391.39,2119.32 r0 bottom value=0
R155 "MCT06030Z0000ZP500" 0603 745.83,1998.11 r0 bottom value=0
R156 "CRCW0402100KFKED" 0402L 249.2,1857.13 r90 bottom value=100k
R157 "CRCW040210K0FKED" 0402L 415.68,2424.24 r180 top value=10.0k
R158 "CRCW040210K0FKED" 0402L 415.68,2387.24 r0 top value=10.0k
R159 "ERJ-2GE0R00X" FP-ERJ-2GE0R00X_0402-MFG 305.44,2568.79 r180 top value=0
R160 "ERJ-2GE0R00X" FP-ERJ-2GE0R00X_0402-MFG 304.95,2618.33 r180 top value=0
R161 "CRCW040210K0FKED" 0402L 664.87,2528.79 r0 top value=10.0k
R162 "CRCW040210K0FKED" 0402L 645.19,2588.47 r270 top value=10.0k
R163 "CRCW0402100KFKED" 0402L 1096.46,1959.65 r270 top value=100k
R164 "CRCW040210K0FKED" 0402L 858.69,1400.77 r90 top value=10.0k
R165 "CRCW040210K0FKED" 0402L 866.24,933.61 r0 top value=10.0k
R166 "CRCW040210K0FKED" 0402L 299.24,1022.1 r0 bottom value=10.0k
R167 "CRCW040210K0FKED" 0402L 1244.67,528.88 r180 bottom value=10.0k
R168 "CRCW040210K0FKED" 0402L 1291.83,464.81 r270 bottom value=10.0k
R169 "ERJ-2GEJ101X" 0402L 1674.64,1638.59 r270 bottom value=100
R170 "ERJ-2GE0R00X" FP-ERJ-2GE0R00X_0402-MFG 1697.45,1701.9 r0 bottom value=0
R171 "ERJ-2GEJ511X" 0402L 1400.12,555.07 r180 top value=510
R172 "ERJ-2GEJ511X" 0402L 1594.9,984.47 r180 top value=510
R173 "CRCW0402100KFKED" 0402L 2422.35,1817.13 r90 bottom value=100k
R174 "ERJ-2RKF1001X" 0402 1811.68,541.76 r0 top value=1.00k
R175 "ERJ-2GE0R00X" FP-ERJ-2GE0R00X_0402-MFG 1969.38,1997.45 r0 bottom value=0
R176 "ERJ-2GE0R00X" FP-ERJ-2GE0R00X_0402-MFG 269.38,1797.45 r0 bottom value=0
R177 "ERJ-2GE0R00X" FP-ERJ-2GE0R00X_0402-MFG 2372.18,1797.45 r0 bottom value=0
R178 "ERJ-2GE0R00X" FP-ERJ-2GE0R00X_0402-MFG 269.38,1697.45 r0 bottom value=0
R179 "ERJ-2GEJ511X" 0402L 1551.59,789.67 r180 top value=510
R180 "ERJ-2GE0R00X" FP-ERJ-2GE0R00X_0402-MFG 269.38,1762.45 r0 bottom value=0
R181 "ERJ-2GE0R00X" FP-ERJ-2GE0R00X_0402-MFG 994.75,2319.98 r270 bottom value=0
R182 "ERJ-2GE0R00X" FP-ERJ-2GE0R00X_0402-MFG 1957.89,1658.52 r0 bottom value=0
R183 "ERJ-2GE0R00X" FP-ERJ-2GE0R00X_0402-MFG 2372.18,1597.45 r0 bottom value=0
R184 "CRCW040210K0FKED" 0402L 1373.2,643.29 r180 bottom value=10.0k
R185 "CRCW04022K20JNED" 0402L 1270.18,587.63 r270 bottom value=2.2k
R186 "CRCW040233R2FKED" 0402 864.5,1280.4 r90 bottom value=33.2
R187 "CRCW040233R2FKED" 0402 917.47,1433.88 r180 bottom value=33.2
R188 "ERJ-2GE0R00X" FP-ERJ-2GE0R00X_0402-MFG 966.13,2251.35 r270 bottom value=0
R189 "ERJ-2GE0R00X" FP-ERJ-2GE0R00X_0402-MFG 1057.36,1455.91 r0 bottom value=0
R190 "ERJ-2GE0R00X" FP-ERJ-2GE0R00X_0402-MFG 905.18,2073.18 r0 bottom value=0
R191 "ERJ-2RKF1001X" 0402 1596.96,2375.29 r90 bottom value=1.00k
R192 "WSL1206R0400FEB" FP-WSL1206R0400FEB_1206-MFG 1048.58,3197.98 r0 bottom value=40m
R193 "WSL1206R0200FEB" FP-WSL1206R0200FEB_1206-MFG 2236.49,1694.93 r180 top value=20m
R194 "ERJ-2RKF1001X" 0402 1549.54,2375.29 r90 bottom value=1.00k
R195 "ERJ-2RKF1001X" 0402 1500.19,2375.63 r90 bottom value=1.00k
R196 "ERJ-2RKF1001X" 0402 1449.62,2375.63 r90 bottom value=1.00k
R197 "ERJ-2GE0R00X" FP-ERJ-2GE0R00X_0402-MFG 1058.48,1325.84 r270 top value=0
R198 "ERJ-2GE0R00X" FP-ERJ-2GE0R00X_0402-MFG 269.38,1662.45 r0 bottom value=0
R199 "ERJ-2GE0R00X" FP-ERJ-2GE0R00X_0402-MFG 860.53,1307.7 r270 top value=0
R200 "WSL1206R0400FEB" FP-WSL1206R0400FEB_1206-MFG 914.18,2636.19 r0 bottom value=40m
R201 "ERJ-2GE0R00X" FP-ERJ-2GE0R00X_0402-MFG 2372.18,1497.45 r0 bottom value=0
R202 "CRCW040249R9FKED" 0402L 1708.21,2126.64 r90 bottom value=49.9
R203 "CRCW040210K0FKED" 0402L 170.45,402.79 r90 top value=10.0k
R204 "CRCW04027K87FKED" 0402L 420.37,520.9 r0 top value=7.87k
R205 "CRCW040282K5FKED" 0402L 420.37,324.05 r180 top value=82.5k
